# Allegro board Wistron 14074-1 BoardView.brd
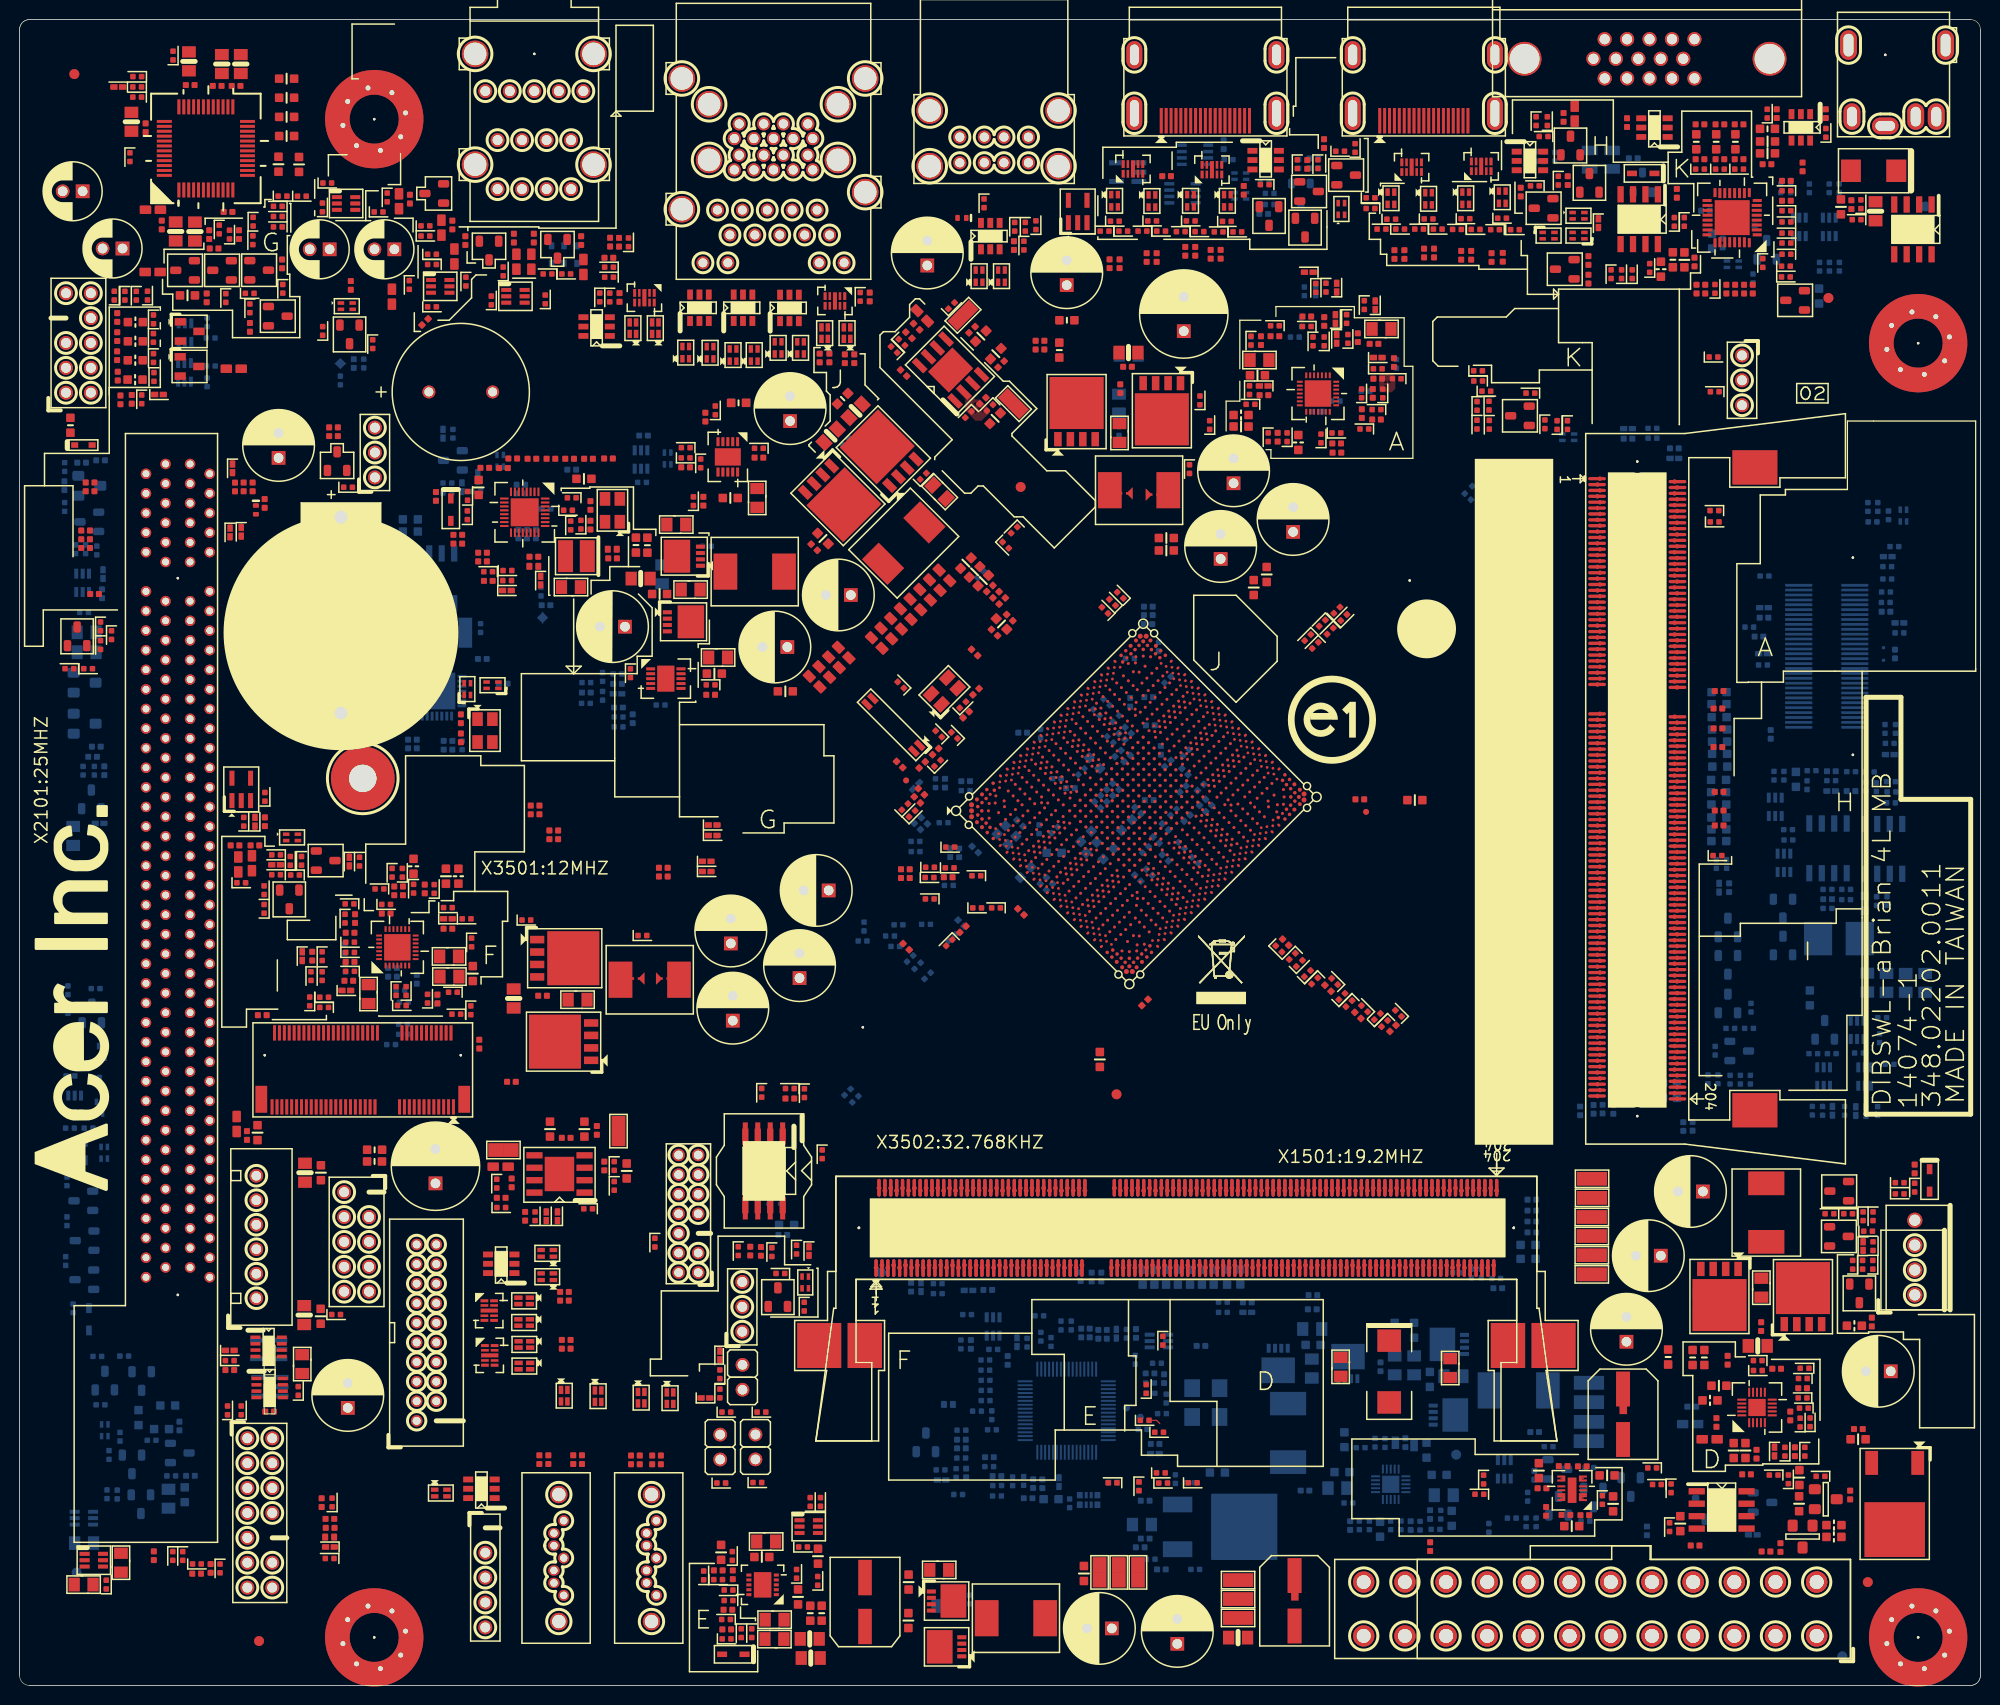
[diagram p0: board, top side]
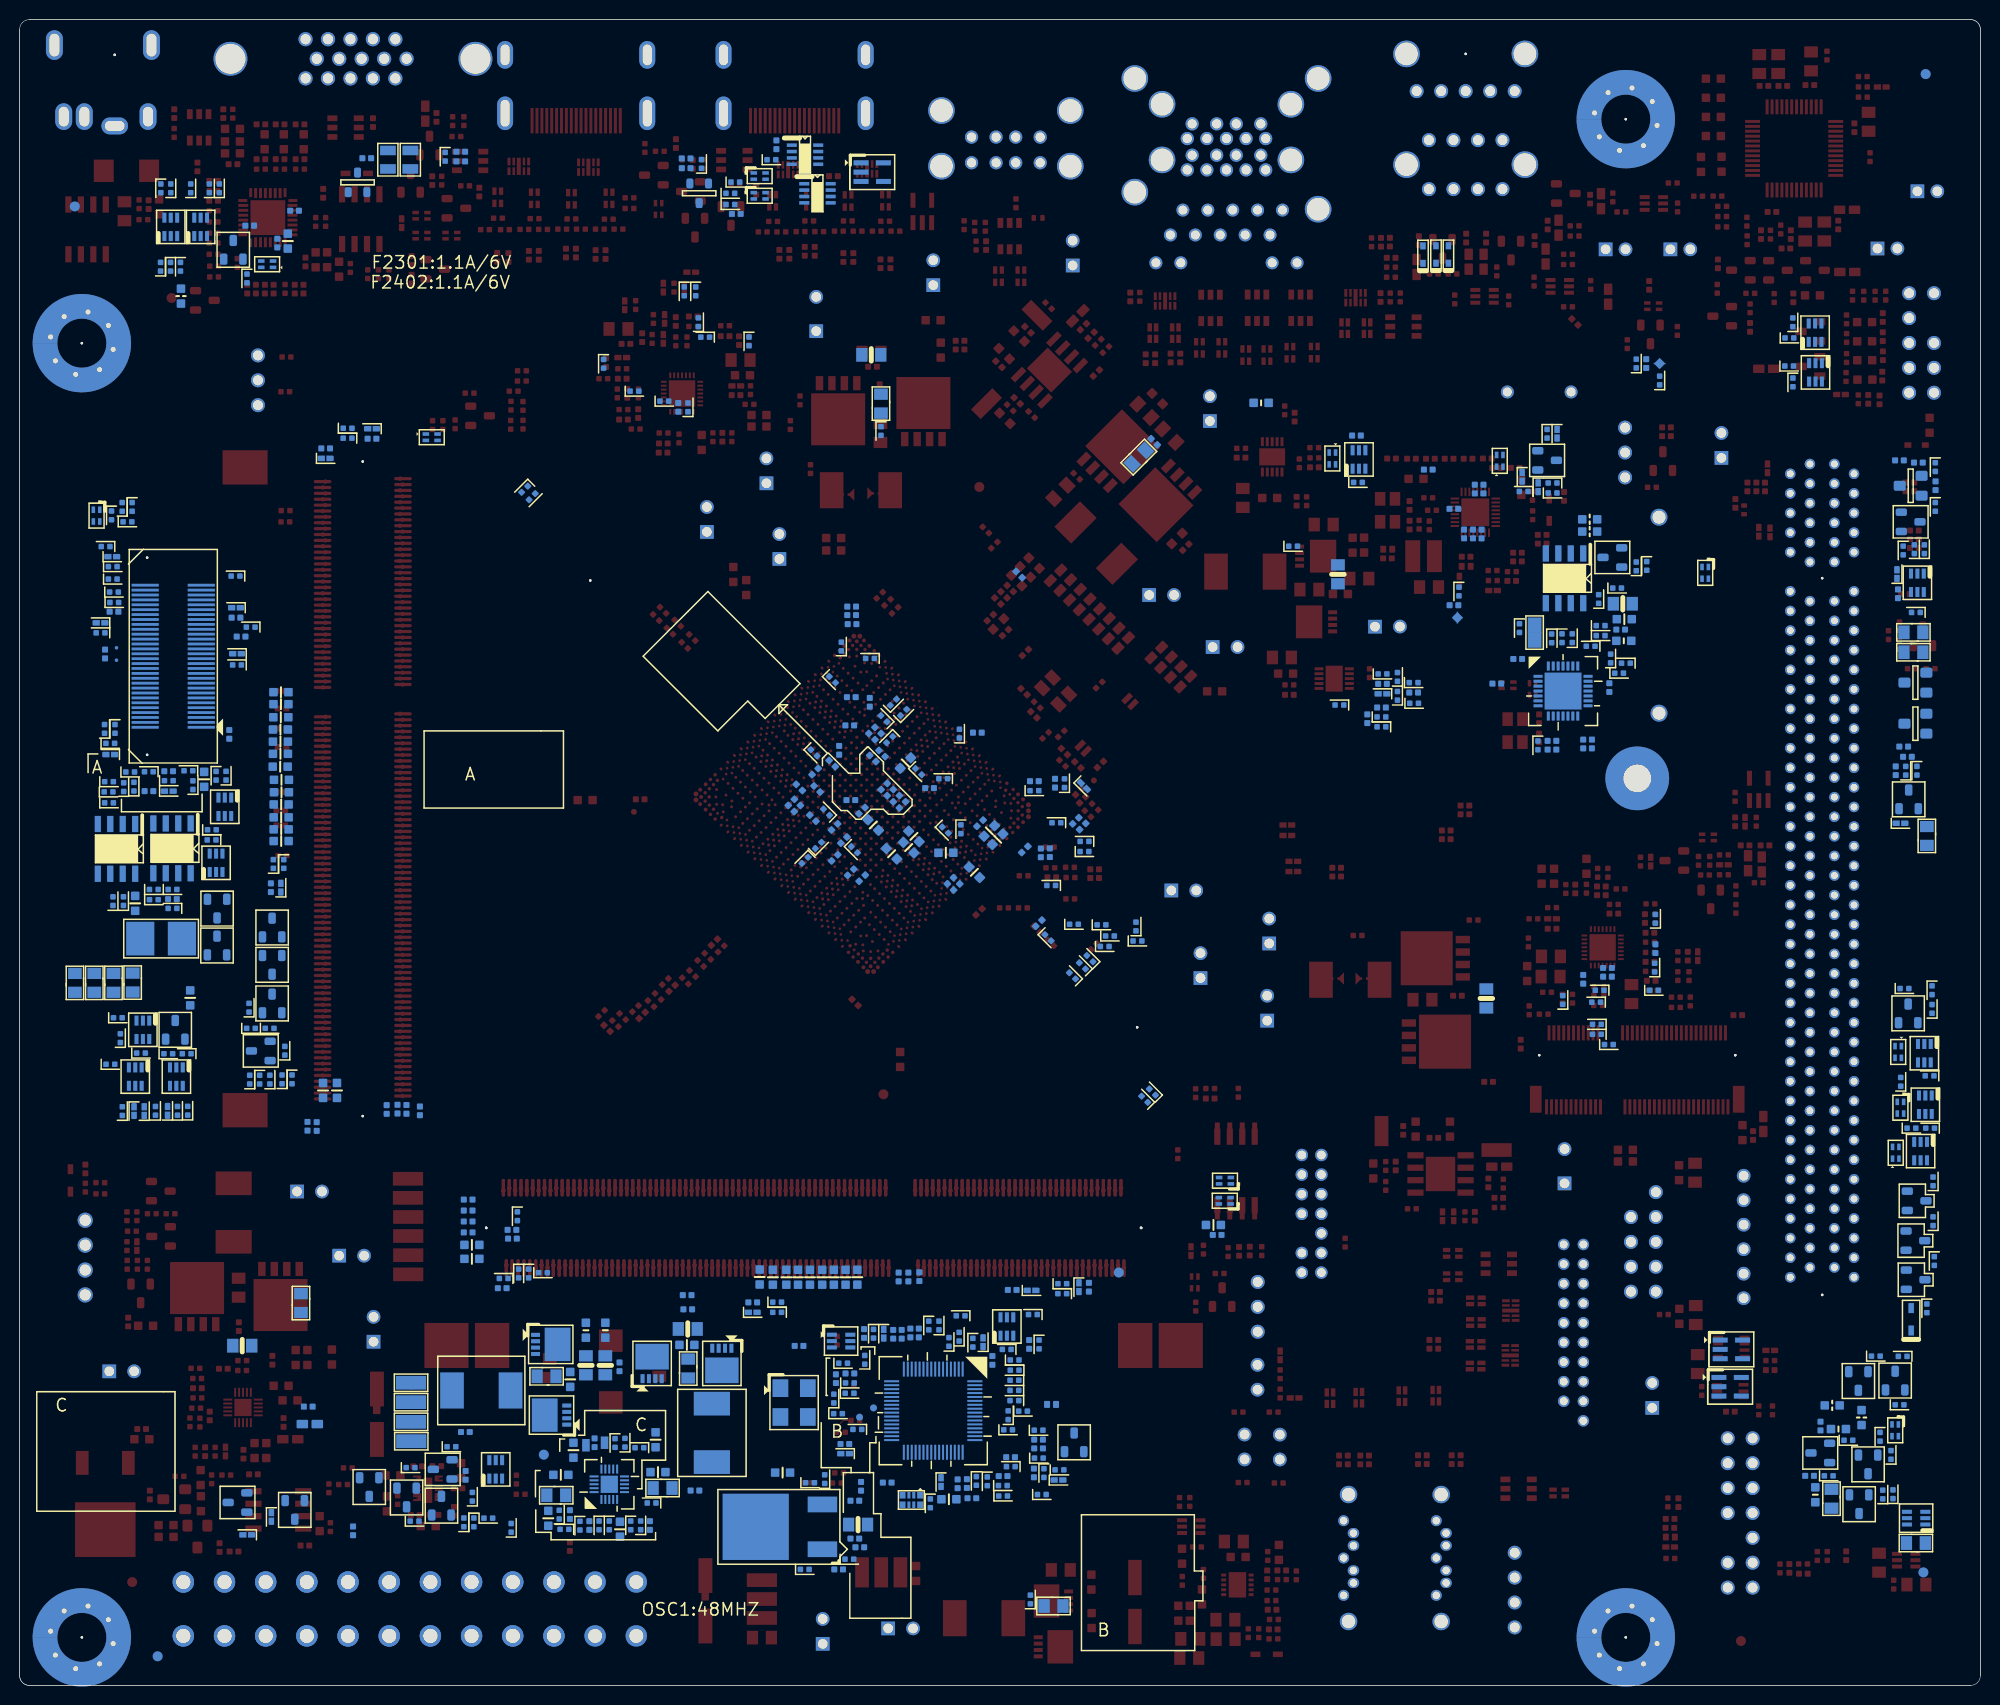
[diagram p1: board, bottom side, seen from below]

Outline 200 x 170 mm; copper layers: TOP, L2VCC, L3, BOTTOM. Coordinates in mm from the lower left corner of the outline.
Outline path: 0,169 0,1 ; 0,169 arc(0.29,169.71) 1,170 ; 0,169 arc(0.29,169.71) 1,170 ; 0,169 0,1 ; 0,1 arc(0.29,0.29) 1,0 ; 1,170 199,170 ; 1,170 199,170 ; 199,170 arc(199.71,169.71) 200,169 ; 1,0 199,0 ; 1,0 199,0 ; 199,0 arc(199.71,0.29) 200,1 ; 199,0 arc(199.71,0.29) 200,1 ; 200,169 200,1 ; 200,169 200,1 ; 33.62,92.57 arc(35,93.95) 36.38,92.57 arc(35,91.19) 33.62,92.57

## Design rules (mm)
constraint set DEFAULT: min track width 0.127, pair gap 0.102
net group POWER_50_8: nets -12V SIO_GND
net group PWR_300_10: nets +3D3V_PWR +5V_PWR
net group PWR_500_10: nets 1D35V_DDR 1P05V_A
net group 50_VGA: nets CRT_B CRT_G CRT_HSYNC_CON CRT_R CRT_VSYNC_CON VGA_BLUE_P VGA_GREEN_P VGA_HSYNC VGA_RED_P VGA_VSYNC
net group AUDIO_4_6: nets 3.3_POP ANTI-POP_GPIO1 ANTI-POP_GPIO1_L ANTI-POP_GPIO1_R AZRST EAPD_DEPOP FP_AUDIO_PRESENCE*_C FP_AUDIO_PRESENCE_N_1 FP_OUTR_SENSE FRONT_JD HDA_SPKR JDREF LINE2_JD LINEIN_JD MIC1_JD MIC2_JD MUTE_R MUTE_RR PCH_SPKR1 SENSE_A SENSE_B
net group AUDIO_8_10: nets AUD_IN_L AUD_IN_LL AUD_IN_LL* AUD_IN_LL_1 AUD_IN_R AUD_IN_RR AUD_IN_RR* AUD_IN_RR_1 AUD_MIC1_L AUD_MIC1_LL AUD_MIC1_LL* AUD_MIC1_LL_1 AUD_MIC1_R AUD_MIC1_RR AUD_MIC1_RR* AUD_MIC1_RR_1 AUD_MIC_1L AUD_MIC_1R AUDAMPIN_L AUDAMPIN_L_C AUDAMPIN_R AUDAMPIN_R_C AUDIN_L AUDIN_R FB_AUDOUT_L FB_AUDOUT_R FB_AUDOUTR_L FB_AUDOUTR_L* FB_AUDOUTR_R FB_AUDOUTR_R* FP_MIC2_L FP_MIC2_L_C FP_MIC2_R FP_MIC2_R_C FP_MICVREF_D1 FP_MICVREF_D2 FP_OUT_L FP_OUT_L_C FP_OUT_LL* FP_OUT_R FP_OUT_R_C FP_OUT_RR* FP_OUTR_L FP_OUTR_LL FP_OUTR_R FP_OUTR_RR LINE2_VREFO LINE2_VREFO_D1 LINE2_VREFO_D2 MIC1_VREFO_L MIC1_VREFO_R MIC2-VREFO MIC2_L MIC2_LL MIC2_LL* MIC2_R MIC2_RR MIC2_RR* MUTE
net group CLK_4_12: nets CLK_PCI_DEBUG CLKIN HDA_BITCLK_CODEC HDA_BITCLK_CPU INT_SERIRQ_CPU INT_SERIRQ_OE LPC_CLKOUT0 LPC_CLKOUT1 OSC_TRI PCH_CLK48 PCH_SPI_CLK PCH_SPI_CLK_FLASH PM_CLKRUN# PMU_SUSCLK_CPU SERIRQ_N SIO_CLKIN SIO_PCICLK
net group FAN_4_12: nets CPU_FAN_PWM1 CPU_FAN_TACH1 SYS_FAN_3P_G SYS_FAN_M SYS_FAN_M1 SYS_FAN_TACH1_1 SYS_FAN_TACH1_2 SYSTEM_FAN_PWM1_1 SYSTEM_FAN_PWM1_2 SYSTEM_FAN_PWM1_3
net group HDA_4_6: nets HDA_RST#_CODEC HDA_RST#_CPU HDA_SDIN0_CODEC HDA_SDIN0_CPU HDA_SDOUT_CODEC HDA_SDOUT_CPU HDA_SYNC_CODEC HDA_SYNC_CPU
net group LED_8_8: nets HD_LED_PWR LAN_LED* LAN_LED*_EMI LAN_LED_ACT LAN_LED_ACT_C LAN_LED_ACTIVE LAN_LEDC0 LAN_LEDC1 LAN_LEDC1_E LAN_LEDC1_E1 LAN_LINK_100 LAN_LINK_100_R LAN_LINK_1000 LAN_LINK_1000_R NGFF_LED_BT NGFF_LED_WLAN PWR_LEDC1 PWR_LEDC1_D PWR_LEDJ_C PWR_LEDJ_L PWR_LEDJ_P SATA_LED# SATA_LED_OUT SATA_LED_OUT1
net group LPC_PORT_4_8: nets LAD0_FWH0 LAD1_FWH1 LAD2_FWH2 LAD3_FWH3 LFRAMEJ_FW4 PORT80_SW
net group M_A_CLK_1: nets M_A_DIM1_CLK_DDR1
net group M_A_CMD-CLK: nets M_A_A0 M_A_A1 M_A_A2 M_A_A3 M_A_A4 M_A_A5 M_A_A6 M_A_A7 M_A_A8 M_A_A9 M_A_A10 M_A_A11 M_A_A12 M_A_A13 M_A_A14 M_A_A15 M_A_BS0 M_A_BS1 M_A_BS2 M_A_CAS# M_A_RAS# M_A_WE#
net group M_A_CTRL-CLK: nets M_A_DIM1_CKE0 M_A_DIM1_CKE1 M_A_DIM1_CS#0 M_A_DIM1_CS#1 M_A_DIM1_ODT0 M_A_DIM1_ODT1
net group M_A_DATA_0: nets M_A_DIM1_DM0 M_A_DQ0 M_A_DQ1 M_A_DQ2 M_A_DQ3 M_A_DQ4 M_A_DQ5 M_A_DQ6 M_A_DQ7 M_A_DQS_DN0 M_A_DQS_DP0
net group M_A_DATA_1: nets M_A_DIM1_DM1 M_A_DQ8 M_A_DQ9 M_A_DQ10 M_A_DQ11 M_A_DQ12 M_A_DQ13 M_A_DQ14 M_A_DQ15
net group M_A_DATA_2: nets M_A_DIM1_DM2 M_A_DQ16 M_A_DQ17 M_A_DQ18 M_A_DQ19 M_A_DQ20 M_A_DQ21 M_A_DQ22 M_A_DQ23
net group M_A_DATA_3: nets M_A_DIM1_DM3 M_A_DQ24 M_A_DQ25 M_A_DQ26 M_A_DQ27 M_A_DQ28 M_A_DQ29 M_A_DQ30 M_A_DQ31 M_A_DQS_DN3
net group M_A_DATA_4: nets M_A_DIM1_DM4 M_A_DQ32 M_A_DQ33 M_A_DQ34 M_A_DQ35 M_A_DQ36 M_A_DQ37 M_A_DQ38 M_A_DQ39
net group M_A_DATA_5: nets M_A_DIM1_DM5 M_A_DQ40 M_A_DQ41 M_A_DQ42 M_A_DQ43 M_A_DQ44 M_A_DQ45 M_A_DQ46 M_A_DQ47 M_A_DQS_DP5
net group M_A_DATA_6: nets M_A_DIM1_DM6 M_A_DQ48 M_A_DQ49 M_A_DQ50 M_A_DQ51 M_A_DQ52 M_A_DQ53 M_A_DQ54 M_A_DQ55
net group M_A_DATA_7: nets M_A_DIM1_DM7 M_A_DQ56 M_A_DQ57 M_A_DQ58 M_A_DQ59 M_A_DQ60 M_A_DQ61 M_A_DQ62 M_A_DQ63
net group M_B_CMD-CLK: nets M_B_A0 M_B_A1 M_B_A2 M_B_A3 M_B_A4 M_B_A5 M_B_A6 M_B_A7 M_B_A8 M_B_A9 M_B_A10 M_B_A11 M_B_A12 M_B_A13 M_B_A14 M_B_A15 M_B_BS0 M_B_BS1 M_B_BS2 M_B_CAS# M_B_RAS# M_B_WE#
net group M_B_CTRL_CLK: nets M_B_DIM2_CKE0 M_B_DIM2_CKE1 M_B_DIM2_CS#0 M_B_DIM2_CS#1 M_B_DIM2_ODT0 M_B_DIM2_ODT1
net group M_B_DATA_0: nets M_B_DIM2_DM0 M_B_DQ0 M_B_DQ1 M_B_DQ2 M_B_DQ3 M_B_DQ4 M_B_DQ5 M_B_DQ6 M_B_DQ7
net group M_B_DATA_1: nets M_B_DIM2_DM1 M_B_DQ8 M_B_DQ9 M_B_DQ10 M_B_DQ11 M_B_DQ12 M_B_DQ13 M_B_DQ14 M_B_DQ15
net group M_B_DATA_2: nets M_B_DIM2_DM2 M_B_DQ16 M_B_DQ17 M_B_DQ18 M_B_DQ19 M_B_DQ20 M_B_DQ21 M_B_DQ22 M_B_DQ23
net group M_B_DATA_3: nets M_B_DIM2_DM3 M_B_DQ24 M_B_DQ25 M_B_DQ26 M_B_DQ27 M_B_DQ28 M_B_DQ29 M_B_DQ30 M_B_DQ31
net group M_B_DATA_4: nets M_B_DIM2_DM4 M_B_DQ32 M_B_DQ33 M_B_DQ34 M_B_DQ35 M_B_DQ36 M_B_DQ37 M_B_DQ38 M_B_DQ39
net group M_B_DATA_5: nets M_B_DIM2_DM5 M_B_DQ40 M_B_DQ41 M_B_DQ42 M_B_DQ43 M_B_DQ44 M_B_DQ45 M_B_DQ46 M_B_DQ47
net group M_B_DATA_6: nets M_B_DIM2_DM6 M_B_DQ48 M_B_DQ49 M_B_DQ50 M_B_DQ51 M_B_DQ52 M_B_DQ53 M_B_DQ54 M_B_DQ55
net group M_B_DATA_7: nets M_B_DIM2_DM7 M_B_DQ56 M_B_DQ57 M_B_DQ58 M_B_DQ59 M_B_DQ60 M_B_DQ61 M_B_DQ62 M_B_DQ63
net group OCP_4_8: nets ADP_OCP OCP_0 OCP_1 OCP_2 OCP_3 OCP_4 OCP_5 OCP_6 OCP_7 OCP_8
net group OTHER_4_5: nets AC_PRESENT_CPU BOARD1 BVCCRTC_EXTPAD CFG0 CFG1 CFG2 CFG3 CFG4 CFG5 CFG6 CFG7 CFG8 COPEN_N CPU_VSS2 CPU_VSS16 DP_HPD_CPU# DP_HPD_RTD2168 DSW_EUP_SEL EDM_SOC EEPROM_WP FP_AUDIO_PRESENCE_N FP_RESET*_R GFX_CLKREQ_CPU# GFX_CLKREQ_CPU#_1D8 GFX_REQ#_Q_B GP_CAMERASB00 GP_CAMERASB01 GP_CAMERASB02 GP_CAMERASB03 GP_CAMERASB04 GP_CAMERASB05 GP_CAMERASB06 GP_CAMERASB07 GP_CAMERASB08 GP_CAMERASB09 GP_CAMERASB11 GPIO_SUS1 GPIO_SUS2 GPIO_SUS3 GPIO_SUS4 GPIO_SUS5 H_PROCHOT# H_PROCHOT#_R HDMI1_DDCCLK_G HDMI1_DDCDATA_G HDMI1_HPD_CON HDMI1_HPD_CPU# HDMI2_DDCCLK_G HDMI2_DDCDATA_G HDMI2_HPD_CON HDMI2_HPD_CPU# HUB_OC14_L HUB_OC23_L HUB_PGANG HUB_PSELF KA20GATE KBCLK KBDATA KBRST_N LAN_CLKREQ_CPU# LAN_CLKREQB LAN_WAKEB LOM_WAKE_N_CPU LOM_WAKE_N_CPU1 LOM_WAKE_N_CPU2 MSCLK MSDATA PCH_SPI_WP# PCH_SPI_WP#_FLASH PCIE_CLKREQ2_CPU#_1D8 PCIE_PRSNT1# PCIE_WAKE_LOM PCIE_WAKE_LOM1 PCIE_WAKE_N_CPU PCIE_WAKE_N_CPU1 PCIE_WAKE_N_CPU2 PCIE_WAKE_N_CPU3 PCIE_WAKE_N_MINI PCIE_WAKE_N_X16 PCU_SMB_ALERT# RSVD# RTD2168_RRX RTD2168_SMBUS_ON RTD2168_SMBUS_ON_1 SDMMC1_RCOMP SDMMC3_RCOMP SEC_GPIO_SUS8 SEC_GPIO_SUS9 SEC_GPIO_SUS10 SIO_GP31 SIO_GP31_R SIO_GP32 SIO_GP32_R SOC_EXTSMI_N SOC_RUNTIME_SCI# SOC_WAKE_SCI_N SP1_DCD_N SP1_DTR_N SP1_RTS_N SP1_RXD SP1_TXD SPI_WP_N_PU SUS_PWRDN_ACK_CPU THERMAL_SHUT# THERMAL_SHUT#_1 TXE_1 TXE_2 USB_OC#_0 USB_OC#_1 USB_OTG_ID USB_VBUSSNS VSS5 W1_DISABLE_N W3_DISABLE W3_DISABLE_N WLAN_CLKREQ_CPU# WLAN_CLKREQ_CPU#_1D8 WLAN_REQ#_Q_B
net group OTHER_4_8: nets GPIO_RCOMP18 HDMI1_LS_R HDMI2_LS_R HUB_RESET# HUB_RREF HUB_SDA HUB_TEST/SCL ICLKICOMP ICLKRCOMP LAN_ISOLATEB LAN_RSET LPC_PME_N M_A_RCOMP_0 M_B_RCOMP_0 MCSI_COMP NGFF_SUSCLK PCH_SPI_CS0# PCH_SPI_CS0#_FLASH PCH_SPI_HOLD# PCH_SPI_HOLD#_FLASH PCH_SPI_SI PCH_SPI_SI_FLASH PCH_SPI_SO PCH_SPI_SO_FLASH PM_EXTTS#0 PM_EXTTS#1 PMC_BATLOW# RCOMP_LPC_HVT RTC_INTRUDER RTD2168_LDO_EN SA0_A_0 SA0_B_0 SA1_A_0 SA1_B_0 SIO_PWRLED_N USB30_VCCA_0_EN USB30_VCCA_1_EN USB_HSIC_RCOMP USB_RCOMP USBVCC4_EN USBVCC23_EN VGG_VR_HOT# VNN_VCC_SEN
net group OTHER_10_8: nets DIMM1_VREF_CA DIMM1_VREF_CA_R DIMM1_VREF_DQ DIMM1_VREF_DQ_R DIMM2_VREF_CA DIMM2_VREF_CA_R DIMM2_VREF_DQ DIMM2_VREF_DQ_R DISCHARGE_A DISCHARGE_B DISCHARGE_C DISCHARGE_M M_A_OCAVREF M_A_OCAVREF_R M_A_ODQVREF M_A_ODQVREF_R M_B_OCAVREF M_B_OCAVREF_R M_B_ODQVREF M_B_ODQVREF_R SIO_VCORE SIO_VIN0 SIO_VIN1 SIO_VIN2 SIO_VIN3 SIO_VIN4
net group POWER20: nets SYS_FAN_3P_POWER
net group POWER25_8: nets AUDIO_VREF
net group POWER25_40: nets PWR_1D8V_BOOT PWR_1D8V_BOOT_1 PWR_1D8V_HG PWR_1D8V_HG_1 PWR_1D8V_LG PWR_1D8V_LX PWR_1P05V_BOOT PWR_1P05V_BOOT_1 PWR_1P05V_HG PWR_1P05V_HG_1 PWR_1P05V_LG PWR_1P05V_LX PWR_12V_BOOT PWR_12V_BOOT1 PWR_12V_BT1 PWR_12V_LG PWR_12V_LX PWR_12V_UG PWR_12V_UG1 PWR_DDR_BT PWR_DDR_BT1 PWR_DDR_LG PWR_DDR_LX PWR_DDR_UG PWR_DDR_UG1 PWR_RT8243_BT1 PWR_RT8243_BT1R PWR_RT8243_BT2 PWR_RT8243_BT2R PWR_RT8243_LG1 PWR_RT8243_LG2 PWR_RT8243_LX1 PWR_RT8243_LX2 PWR_RT8243_UG1 PWR_RT8243_UG1R PWR_RT8243_UG2 PWR_RT8243_UG2R PWR_VCC0_BT PWR_VCC0_BTR PWR_VCC0_HG PWR_VCC0_HGR PWR_VCC0_LG PWR_VGG_BT PWR_VGG_BTR PWR_VGG_HG PWR_VGG_HGR PWR_VGG_LG PWR_VGG_SW
net group POWER_7_10: nets VCC0_VCC_SEN VCC0_VSS_SEN VGG_VCC_SEN VGG_VSS_SEN
net group POWER_10_10: nets +VCCCLKDDR_1P24_1P35 +VCCPADCF3SI0_1P8_3P3 +VCCSFRPLLDDR_1P24_1P35 LEDH1_5V PWR_0D675V_EN_S3 PWR_1D5V_EN PWR_1D8V_CS PWR_1D8V_EN PWR_1D8V_RF PWR_1D24V_CNTL PWR_1D24V_EN PWR_1D35V_EN_S5 PWR_1P05V_CS PWR_1P05V_EN PWR_1P05V_EN1 PWR_1P05V_EN2 PWR_1P05V_RF PWR_1P15V_CNTL PWR_1P15V_EN PWR_12V_COMP PWR_12V_CP1 PWR_12V_VOS PWR_AD+_2 PWR_DDR_CS PWR_DDR_TON PWR_DDR_VTTREF PWR_RT8243_EMN PWR_RT8243_ENLDO PWR_RT8243_ENTRIP1 PWR_RT8243_ENTRIP2 PWR_RT8243_PG PWR_VCC0_COMP PWR_VCC0_COMP1 PWR_VCC0_COMP2 PWR_VCC0_CSCOMP PWR_VCC0_CSMP1 PWR_VCC0_CSREF PWR_VCC0_CSSUM PWR_VCC0_DIFFOUT PWR_VCC0_ILIM PWR_VCC0_IMAX PWR_VCC0_IOUT PWR_VCC0_ROSC PWR_VCC0_TSEN PWR_VCC0_TSEN1 PWR_VCC0_VBOOT/ADDR PWR_VCC0_VRMP PWR_VCORE_ENABLE PWR_VGG_COMP PWR_VGG_COMP1 PWR_VGG_COMP2 PWR_VGG_CSCOMP PWR_VGG_CSMP1 PWR_VGG_CSREF PWR_VGG_CSSUM PWR_VGG_DIFFOUT PWR_VGG_ENABLE PWR_VGG_ILIM PWR_VGG_IMAX PWR_VGG_IOUT PWR_VGG_ROSC PWR_VGG_TSEN PWR_VGG_TSEN1 PWR_VGG_VBOOT/ADDR PWR_VGG_VRMP SYS_FAN_FB USB_VDDQ_G31_H44 VCORE_VR_HOT
net group POWER_10_10_20: nets PWR_VCC0_CSN PWR_VCC0_CSP PWR_VCC0_VSN PWR_VCC0_VSP PWR_VGG_CSN PWR_VGG_CSP PWR_VGG_VSN PWR_VGG_VSP
net group POWER_15_20: nets 1D5V_S0 PWR_1D8V_FB PWR_1P05V_FB PWR_1P15V_FB PWR_12V_FB PWR_12V_FB1 PWR_DDR_FB PWR_RT8243_3VFB PWR_RT8243_FB1 PWR_RT8243_FB2 PWR_RT8243_TON PWR_VCC0_FB PWR_VGG_FB
net group POWER_20_10: nets 1D8V_DDI 1D8V_S0 5V_DDC_HDMI11 5V_DDC_HDMI12 5V_DDC_HDMI21 5V_DDC_HDMI22 +3VL +5VL +VCCCFIOAZA_1P80 AD_JK_S AVDD2 BZ_ON BZ_ON1 LDOVDD_IN P_LAN_VDDREG_IN PWR_1D5V_VIN PWR_1D8V_SN PWR_1D8V_VCC PWR_1P05V_SN PWR_1P05V_VCC PWR_12V_SNB PWR_12V_VCC PWR_DDR_SNB PWR_DDR_VDD PWR_DDR_VDDQ PWR_RT8243_BYP1 PWR_RT8243_LDO3 PWR_RT8243_LDO5 PWR_RT8243_SNB1 PWR_RT8243_SNB2 PWR_VCC0_PVCC PWR_VCC0_SN PWR_VCC0_VCC PWR_VGG_PVCC PWR_VGG_SN PWR_VGG_VCC RTD2168_AVCC12 RTD2168_AVCC33 RTD2168_DAC33 V1P5_PWR VGA_DDC_PU
net group POWER_30_10: nets 1D05V_LAN 3D3V_LAN 3D3V_NGFF 3VSB_DET 5V_HUB HUB_AVDD HUB_DVDD LAN_CONN_CVT P_1.05VLAN_OUT VCC3_3SBREF
net group PWR_12_10: nets 1D8V_SPI
net group PWR_40_10: nets 1D15V_S5 1D24V_S5 1P15V_A 3D3V_RTD2168 3D3V_S5_PRIME 5V_HDMI 5V_S0_VGA PWR_1D24V_A PWR_1D24V_VIN PWR_1P15V_VIN USB30_VCCA_0 USB30_VCCA_1 USBVCC4 USBVCC23
net group PWR_80_10: nets 0D675V_S0 12V_VIN +DCBATOUT_RT8243_1 PWR_1D8V_VIN PWR_DDR_LDOIN PWR_DDR_VTT PWR_VGG_VIN
net group PWR_200_10: nets +12V DDR_1D35VIN PWR_1D8V_A PWR_1P05V_VIN
net group RTC_6_10: nets RTC_AUX_S5 VBAT VBAT1 VBAT_SIO
net group SEQUENCE_4_8: nets 1D05V_S5_PG 1D8V_S0_EN1 1D8V_S0_EN2 1D8V_S5_PG 1D15V_S5_PG 1D24V_S5_PG 1D35V_S3_PG 3D3V_S5_PRIME_EN1 3D3V_S5_PRIME_EN2 3D3V_S5_PRIME_EN3 5V_DUAL_EN1 5V_DUAL_EN2 5V_DUAL_EN3 5V_DUAL_EN4 5V_DUAL_EN5 5V_DUAL_EN6 5V_DUAL_EN_5VSB 5V_DUAL_EN_12V 5VSB_CTRL# ADP_12V_S0_PG ADP_EUPPWR_EN1 ADP_EUPPWR_EN2 ADP_EUPPWR_EN3 ADP_EUPPWR_EN4 ADP_EUPPWR_EN5 ADP_EUPPWR_EN6 ADP_EUPPWR_EN7 ADP_NORMPWR_EN ATX_ON1* ATX_ON* ATX_PWRGD ATX_PWRGD_SIO COREPWROK DDR3_DRAM_PWROK DDR3_DRAM_PWROK1 DDR3_DRAM_PWROK2 DDR3_VCCA_PWRGD_3D3V DDR3_VCCA_PWROK DDR3_VCCA_PWROK1 DIMM1_DRAMRST# DIMM2_DRAMRST# M_A_DRAMRST# M_B_DRAMRST# PCIE_RST_X1 PCIRST_LAN# PLT_RST# PLT_RST#_CPU PLT_RST#_CPU1 PLT_RST#_CPU2 PLT_WLAN_RST# PLTRST_SIO_N PM_PWRBTN#_CPU PM_PWRBTN#_CPU1 PM_SLP_S0IX PM_SLP_S0IX_CPU PM_SLP_S0IX_CPU1 PM_SLP_S0IX_CPU2 PM_SLP_S3#_CPU PM_SLP_S4#_CPU PMC_RSTBTN# PWR_12V_ENABLE1 PWR_12V_ENABLE2 PWR_BTN_N PWR_BTNJ_C PWRGD3V_150MS PWRGD_PS_L PWRGD_PS_L1 RSMRST#_CPU RSMRST#_R RSMRST_N RTC_RST#_DOWN SIO_EUP_EN SIO_LAN_RST SIO_PB_IN SIO_PSON_N SIO_PSON_N_1 SIO_PWNBTN_N SIO_PWRGD SLP_S3#_LS1 SLP_S3#_LS2 SLP_S3_N SLP_S3_N_B SLP_S4#_LS1 SLP_S4#_LS2 SLP_S4_N SYS_PWRGD SYS_PWRGD1 SYS_PWRGD2 SYS_PWRGD3 SYS_PWRGD4 VCORE_PG VGG_PG VTT_CT_3.3V_NORM VTT_CT_5VC_NORM
net group SIO_SYS_THERMDA: nets HWM_REF SYS_THERMDA VRD_THERMDA
net group SMB_4_10: nets APU_SIC APU_SID CIIC_SCL CIIC_SDA CRT_DDCCLK_CON CRT_DDCDATA_CON HDMI1_DDCCLK_CON HDMI1_DDCCLK_CPU HDMI1_DDCDATA_CON HDMI1_DDCDATA_CPU HDMI2_DDCCLK_CON HDMI2_DDCCLK_CPU HDMI2_DDCDATA_CON HDMI2_DDCDATA_CPU POL1_SDA POL2_SCL SMB_CLK SMB_CLK_2168 SMB_CLK_CPU SMB_CLK_M SMB_CLK_MINI SMB_CLK_XDP SMB_DATA SMB_DATA_2168 SMB_DATA_CPU SMB_DATA_M SMB_DATA_MINI SMB_DATA_XDP UART0_RXD UART0_TXD UART_RXD UART_TXD VGA_DDC_CLK VGA_DDC_DATA
net group SVID_4_15: nets SVID_ALERT#_CPU SVID_ALERT#_VCORE SVID_ALERT#_VGG SVID_CLK_CPU SVID_CLK_VCORE SVID_CLK_VGG SVID_DATA_CPU SVID_DATA_VCORE SVID_DATA_VCORE_R SVID_DATA_VGG SVID_DATA_VGG_R
net group XDP_4_5: nets PM_PWRBTN#_XDP TP_CLK_ITP_100M_CK505_DN TP_CLK_ITP_100M_CK505_DP XDP_COREPWROK XDP_HLT_BOOT XDP_PMU_RSTBTN_N XDP_PRDY# XDP_PREQ# XDP_PREQ#_C XDP_PRESENT_N XDP_RSMRST_N XDP_RST#_R XDP_TCK XDP_TDI XDP_TDO XDP_TMS XDP_TRST#
net group XTAL_4_12: nets BLAN_XTALI BLAN_XTALI_1 BLAN_XTALO HUB_X1 HUB_X2 RTC_RST# RTC_X1 RTC_X2 SRTC_RST# XTAL19D2M_IN XTAL19D2M_OUT

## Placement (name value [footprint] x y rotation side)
ATX1  JWT-CONN24B-S1-GP  [C4201WV0-B2X12P]  160.2 7.8 180 top
ATX2  TCN-CONN20B-1GP  [PPA12635GD210F]  164.4 7.8 180 top
AUDH1  JWT-CONN10D-SFP7-GP  [1E450400]  6 137 270 top
AUDIO1  ALC662-GR-GP  [PFPCC48-1H63]  19 156.85 180 top
AUDR1  AUDIO-JK187-GP  [ABA-JAK-028-K03]  52.5 166.5 0 top
BT1  BAT-AAA-BAT-029-K01-GP-U  [AAA-BAT-029-K01]  32.78 107.42 90 top
BUZ1  BUZZER-17-GP-U  [AC-1205G-N1LF-U]  45 132 90 top
C20  SCD1U16V2KX-3GP  [C402H22]  181.86 154.97 0 top
C501  SCD1U16V2KX-3GP  [C402H22]  136.5 68.38 225 top
C502  SCD1U16V2KX-3GP  [C402H22]  133.45 71.15 225 top
C503  SCD1U16V2KX-3GP  [C402H22]  129.13 75.84 225 top
C504  SCD1U16V2KX-3GP  [C402H22]  140.08 67.06 315 top
C1001  SC1U10V2KX-1GP  [C402H22]  111.2 91.11 45 bottom
C1002  SC1U10V2KX-1GP  [C402H22]  98.96 111.94 135 top
C1003  SC1U10V2KX-1GP  [C402H22]  98.05 113.36 315 bottom
C1004  SC1U10V2KX-1GP  [C402H22]  116.86 84.46 225 bottom
C1005  SC1U10V2KX-1GP  [C402H22]  112.44 97.46 315 bottom
C1006  SC1U10V2KX-1GP  [C402H22]  113.07 96.83 315 bottom
C1007  SC1U10V2KX-1GP  [C402H22]  100.99 108.97 45 top
C1008  SC1U10V2KX-1GP  [C402H22]  99.59 111.3 135 top
C1009  SC22U6D3V3MX-1-GP  [C603H40]  98.3 112.75 135 top
C1010  SC22U6D3V3MX-1-GP  [C603H40]  97.41 113.64 135 top
C1011  SC22U6D3V3MX-1-GP  [C603H40]  96.52 114.53 135 top
C1012  SC22U6D3V3MX-1-GP  [C603H40]  100.15 108.32 45 top
C1013  SC1U10V2KX-1GP  [C402H22]  110.58 90.49 45 bottom
C1017  SC1U10V2KX-1GP  [C402H22]  119.09 88.51 315 bottom
C1018  SC1U10V2KX-1GP  [C402H22]  97.41 105.41 45 top
C1020  SC1U10V2KX-1GP  [C402H22]  111.82 91.74 45 bottom
C1022  SC1U10V2KX-1GP  [C402H22]  109.95 89.86 45 bottom
C1024  SC1U10V2KX-1GP  [C402H22]  99.44 107.44 45 top
C1025  SC1U10V2KX-1GP  [C402H22]  100.23 110.67 135 top
C1026  SC1U10V2KX-1GP  [C402H22]  90.42 75.39 225 top
C1027  SC1U10V2KX-1GP  [C402H22]  118.86 93.26 45 bottom
C1030  SC1U10V2KX-1GP  [C402H22]  114.08 89.28 45 bottom
C1031  SC10U6D3V3MX-GP  [C603H38]  105.52 84.97 90 bottom
C1032  SC1U10V2KX-1GP  [C402H22]  117.12 94.08 315 bottom
C1033  SC1U10V2KX-1GP  [C402H22]  116.41 95.43 0 bottom
C1034  SC1U10V2KX-1GP  [C402H22]  104.42 81.48 225 bottom
C1035  SC1U10V2KX-1GP  [C402H22]  96.04 77.79 45 bottom
C1037  SC1U10V2KX-1GP  [C402H22]  120.47 91.64 315 bottom
C1040  SC22U6D3V3MX-1-GP  [C603H40]  125.88 112.04 0 top
C1041  SC22U6D3V3MX-1-GP  [C603H40]  116.97 115.82 270 top
C1042  SC22U6D3V3MX-1-GP  [C603H40]  127.2 113.37 0 top
C1043  SC10U6D3V3MX-GP  [C603H38]  102.61 82.98 135 bottom
C1044  SC10U6D3V3MX-GP  [C603H38]  111.06 84.87 135 bottom
C1045  SC10U6D3V3MX-GP  [C603H38]  109.32 85.5 135 bottom
C1046  SC10U6D3V3MX-GP  [C603H38]  112.93 87.81 315 bottom
C1047  SC1U10V2KX-1GP  [C402H22]  105.05 82.12 225 bottom
C1048  SC22U6D3V3MX-1-GP  [C603H40]  116.97 117.09 270 top
C1049  SC10U6D3V3MX-GP  [C603H38]  108.78 86.64 135 bottom
C1056  SC1U10V2KX-1GP  [C402H22]  112.03 95.1 135 bottom
C1057  SC1U10V2KX-1GP  [C402H22]  112.97 94.59 135 bottom
C1102  SC1U10V2KX-1GP  [C402H22]  102.13 78.94 225 top
C1103  SC1U10V2KX-1GP  [C402H22]  102.31 97.23 270 bottom
C1104  SC22U6D3V3MX-1-GP  [C603H40]  100.24 86.36 225 bottom
C1105  SC1U10V2KX-1GP  [C402H22]  95.83 84.96 180 bottom
C1108  SC1U10V2KX-1GP  [C402H22]  113.28 100.33 180 bottom
C1110  SC1U10V2KX-1GP  [C402H22]  94.92 84.98 180 bottom
C1111  SC1U10V2KX-1GP  [C402H22]  97.47 85.31 225 bottom
C1113  SC1U10V2KX-1GP  [C402H22]  102.04 87.99 225 bottom
C1114  SC22U6D3V3MX-1-GP  [C603H40]  101.09 87.2 225 bottom
C1115  SC1U10V2KX-1GP  [C402H22]  91.57 87.66 225 bottom
C1116  SC1U10V2KX-1GP  [C402H22]  115.33 97.97 270 bottom
C1118  SC1U10V2KX-1GP  [C402H22]  116.87 87.61 225 bottom
C1119  SC1U10V2KX-1GP  [C402H22]  115.92 86.27 225 bottom
C1120  SC22U6D3V3MX-1-GP  [C603H40]  114.55 41.66 0 bottom
C1121  SC1U10V2KX-1GP  [C402H22]  107.19 91.57 90 bottom
C1122  SC22U6D3V3MX-1-GP  [C603H40]  110.19 63.88 0 top
C1123  SC22U6D3V3MX-1-GP  [C603H40]  142.32 90.35 270 top
C1124  SC22U6D3V3MX-1-GP  [C603H40]  173.35 98.81 270 bottom
C1126  SC1U10V2KX-1GP  [C402H22]  91.57 90.37 225 top
C1127  SC1U10V2KX-1GP  [C402H22]  91.97 91.21 225 top
C1128  SC1U10V2KX-1GP  [C402H22]  115.09 108.31 270 bottom
C1130  SC22U6D3V3MX-1-GP  [C603H40]  109.64 94.13 45 bottom
C1132  SC1U10V2KX-1GP  [C402H22]  89.76 93.98 225 top
C1133  SC1U10V2KX-1GP  [C402H22]  92.28 88.24 225 bottom
C1134  SC1U10V2KX-1GP  [C402H22]  115.17 100.85 270 bottom
C1137  SC1U10V2KX-1GP  [C402H22]  115.13 110.09 270 bottom
C1138  SC1U10V2KX-1GP  [C402H22]  115.13 109.23 270 bottom
C1201  SC10U6D3V3MX-GP  [C603H38]  173.32 88.58 270 bottom
C1202  SC10U6D3V3MX-GP  [C603H38]  173.34 100.14 270 bottom
C1203  SC10U6D3V3MX-GP  [C603H38]  173.29 91.15 270 bottom
C1204  SC10U6D3V3MX-GP  [C603H38]  173.34 101.36 270 bottom
C1205  SC10U6D3V3MX-GP  [C603H38]  173.32 86.17 270 bottom
C1206  SC10U6D3V3MX-GP  [C603H38]  173.32 87.36 270 bottom
C1207  SC10U6D3V3MX-GP  [C603H38]  173.4 97.55 270 bottom
C1208  SC10U6D3V3MX-GP  [C603H38]  173.32 89.9 270 bottom
C1209  SC1U10V2KX-1GP  [C402H22]  114.05 82.38 225 bottom
C1210  SC1U10V2KX-1GP  [C402H22]  173.23 95.76 90 top
C1211  SC1U10V2KX-1GP  [C402H22]  173.23 97.66 90 top
C1212  SC1U10V2KX-1GP  [C402H22]  173.35 101.47 90 top
C1213  SC1U10V2KX-1GP  [C402H22]  173.35 91.19 90 top
C1214  SC1U10V2KX-1GP  [C402H22]  173.35 89.28 90 top
C1215  SC1U10V2KX-1GP  [C402H22]  115.23 82.98 225 bottom
C1216  SC1U10V2KX-1GP  [C402H22]  136.7 90.42 90 top
C1217  SCD1U16V2KX-3GP  [C402H22]  149.78 46.49 270 bottom
C1218  SCD1U16V2KX-3GP  [C402H22]  149.73 45.59 270 bottom
C1219  SC1U10V2KX-1GP  [C402H22]  162.56 58.78 0 bottom
C1220  SC1U10V2KX-1GP  [C402H22]  161.46 58.81 0 bottom
C1221  SC1U10V2KX-1GP  [C402H22]  160.54 58.79 0 bottom
C1222  SC1U10V2KX-1GP  [C402H22]  159.17 58.63 0 bottom
C1223  SC10U6D3V3MX-GP  [C603H38]  169.05 60.72 0 bottom
C1224  SC10U6D3V3MX-GP  [C603H38]  167.63 60.72 0 bottom
C1225  SCD1U16V2KX-3GP  [C402H22]  125.22 39.09 90 bottom
C1226  SCD1U16V2KX-3GP  [C402H22]  90.93 40.64 180 bottom
C1227  SC1KP50V2KX-1GP  [C402H22]  98.76 40.36 270 bottom
C1230  SC10U6D3V3MX-GP  [C603H38]  173.29 92.42 270 bottom
C1231  SC10U6D3V3MX-GP  [C603H38]  173.42 93.76 270 bottom
C1301  SC10U6D3V3MX-GP  [C603H38]  115.75 41.65 0 bottom
C1302  SC10U6D3V3MX-GP  [C603H38]  116.94 41.65 0 bottom
C1303  SC10U6D3V3MX-GP  [C603H38]  119.38 41.65 0 bottom
C1304  SC10U6D3V3MX-GP  [C603H38]  118.14 41.65 0 bottom
C1305  SC10U6D3V3MX-GP  [C603H38]  121.8 41.65 0 bottom
C1306  SC10U6D3V3MX-GP  [C603H38]  123.17 41.65 0 bottom
C1307  SC10U6D3V3MX-GP  [C603H38]  120.6 41.65 0 bottom
C1308  SC10U6D3V3MX-GP  [C603H38]  124.51 41.68 0 bottom
C1309  SC1U10V2KX-1GP  [C402H22]  109.35 41.68 0 bottom
C1310  SC1U10V2KX-1GP  [C402H22]  121.28 90.12 225 bottom
C1311  SC1U10V2KX-1GP  [C402H22]  108.23 41.71 0 bottom
C1312  SC1U10V2KX-1GP  [C402H22]  114.78 69.7 315 top
C1313  SC1U10V2KX-1GP  [C402H22]  110.34 41.68 0 bottom
C1314  SC1U10V2KX-1GP  [C402H22]  173.23 99.69 90 top
C1315  SCD1U16V2KX-3GP  [C402H22]  173.35 87.76 90 top
C1316  SC1U10V2KX-1GP  [C402H22]  120.67 89.49 225 bottom
C1317  SCD1U16V2KX-3GP  [C402H22]  169.7 57.04 180 bottom
C1318  SCD1U16V2KX-3GP  [C402H22]  170.64 57.06 180 bottom
C1319  SC1U10V2KX-1GP  [C402H22]  154.25 49.58 270 bottom
C1320  SC1U10V2KX-1GP  [C402H22]  154.25 48.46 270 bottom
C1321  SC1U10V2KX-1GP  [C402H22]  154.25 47.34 270 bottom
C1322  SC1U10V2KX-1GP  [C402H22]  154.25 46.23 270 bottom
C1323  SC10U6D3V3MX-GP  [C603H38]  153.87 44.96 270 bottom
C1324  SC10U6D3V3MX-GP  [C603H38]  153.87 43.53 270 bottom
C1325  SCD1U16V2KX-3GP  [C402H22]  174.37 81.41 0 bottom
C1326  SCD1U16V2KX-3GP  [C402H22]  164.06 127.23 270 bottom
C1327  SC1KP50V2KX-1GP  [C402H22]  168.78 126.24 90 bottom
C1330  SC10U6D3V3MX-GP  [C603H38]  173.39 96.32 270 bottom
C1331  SC10U6D3V3MX-GP  [C603H38]  173.39 95.07 270 bottom
C1412  SCD01U50V2KX-1GP  [C402H22]  56.47 23.04 0 top
C1413  SCD01U50V2KX-1GP  [C402H22]  57.36 23.04 0 top
C1417  SCD01U50V2KX-1GP  [C402H22]  53.02 23.04 0 top
C1418  SCD01U50V2KX-1GP  [C402H22]  53.93 23.04 0 top
C1419  SCD01U50V2KX-1GP  [C402H22]  65.41 23.01 0 top
C1420  SCD01U50V2KX-1GP  [C402H22]  62.37 23.01 0 top
C1421  SCD01U50V2KX-1GP  [C402H22]  63.25 23.01 0 top
C1422  SCD01U50V2KX-1GP  [C402H22]  64.52 23.01 0 top
C1501  SC6D8P50V2CN-GP  [C402H22]  97.55 101.42 135 top
C1502  SC6D8P50V2CN-GP  [C402H22]  96.55 99.06 315 top
C1801  SCD1U16V2KX-3GP  [C402H22]  52.58 88.9 90 top
C1802  SCD1U16V2KX-3GP  [C402H22]  52.58 89.79 90 top
C1803  SC22P50V2JN-4GP  [C402H22]  22.38 148.06 180 top
C1901  SCD1U16V2ZY-2GP  [C402H22]  7.19 121.87 90 top
C1902  SCD1U16V2ZY-2GP  [C402H22]  160.02 143.51 180 top
C1903  SCD1U16V2KX-3GP  [C402H22]  96.49 92.28 90 bottom
C1905  SCD1U16V2KX-3GP  [C402H22]  7.65 111.38 270 top
C1906  SCD1U16V2KX-3GP  [C402H22]  6.73 117.86 270 top
C1907  SCD1U16V2KX-3GP  [C402H22]  6.73 116.97 270 top
C1908  SCD1U16V2KX-3GP  [C402H22]  6.73 116.08 270 top
C1909  SCD1U16V2KX-3GP  [C402H22]  23.77 122.31 0 top
C1910  SCD1U16V2KX-3GP  [C402H22]  22.85 122.31 0 top
C1911  SCD1U16V2KX-3GP  [C402H22]  7.19 122.76 270 top
C1912  SCD1U16V2KX-3GP  [C402H22]  24.99 120.62 0 top
C1913  SCD1U16V2KX-3GP  [C402H22]  21.97 122.3 0 top
C2001  SC100P50V2JN-3GP  [C402H22]  111.51 20.7 90 bottom
C2002  SCD1U16V2KX-3GP  [C402H22]  96.06 25.08 90 bottom
C2003  SC1U10V2KX-1GP  [C402H22]  116.74 31.3 0 bottom
C2004  SC4D7U6D3V2MX-GP-U  [C402-TO0D2H26]  94.74 28.68 90 bottom
C2005  SC100P50V2JN-3GP  [C402H22]  100.78 33.17 180 bottom
C2006  SCD1U16V2KX-3GP  [C402H22]  96.06 24.19 90 bottom
C2008  SC1U10V2KX-1GP  [C402H22]  102.87 19.1 270 bottom
C2009  SCD1U16V2KX-3GP  [C402H22]  96.54 21.68 180 bottom
C2010  SC1U10V3ZY-6GP  [C603H36]  105.21 19 90 bottom
C2011  SCD1U16V2KX-3GP  [C402H22]  98.92 23.29 270 bottom
C2012  SCD1U16V2KX-3GP  [C402H22]  109.14 35.97 0 bottom
C2013  SCD1U16V2KX-3GP  [C402H22]  110.03 35.83 0 bottom
C2014  SCD1U16V2KX-3GP  [C402H22]  114.17 20.32 180 bottom
C2015  SCD1U16V2ZY-2GP  [C402H22]  110.89 35.83 180 bottom
C2016  SCD1U16V2KX-3GP  [C402H22]  99.69 21.36 90 bottom
C2017  SC1U10V2KX-1GP  [C402H22]  115.82 24.64 270 bottom
C2018  SCD1U16V2ZY-2GP  [C402H22]  115.31 31.83 90 bottom
C2019  SCD1U16V2KX-3GP  [C402H22]  103.38 20.6 180 bottom
C2020  SCD1U16V2KX-3GP  [C402H22]  104.32 20.58 180 bottom
C2040  SC1U10V2KX-1GP  [C402H22]  108.28 35.97 0 bottom
C2101  SCD1U16V2ZY-2GP  [C402H22]  47.8 112.72 270 top
C2102  SC4D7U6D3V2MX-GP-U  [C402-TO0D2H26]  52.45 114.2 270 top
C2103  SCD1U16V2KX-3GP  [C402H22]  52.46 115.18 270 top
C2104  SCD1U16V2KX-3GP  [C402H22]  56.32 124.07 270 bottom
C2105  SCD1U16V2KX-3GP  [C402H22]  42.47 121.34 0 top
C2106  SC4D7U6D3V2MX-GP-U  [C402-TO0D2H26]  60.45 115.95 90 top
C2107  SCD1U16V2KX-3GP  [C402H22]  51.76 117.51 0 bottom
C2108  SCD1U16V2KX-3GP  [C402H22]  50.88 117.5 0 bottom
C2109  SCD1U16V2KX-3GP  [C402H22]  50.69 122.09 180 bottom
C2110  SCD1U16V2KX-3GP  [C402H22]  51.57 122.09 180 bottom
C2111  SCD1U16V2KX-3GP  [C402H22]  53.71 120.07 90 bottom
C2114  SC1U10V2KX-1GP  [C402H22]  52.66 117.51 0 bottom
C2115  SCD1U16V2KX-3GP  [C402H22]  60.48 115.02 90 top
C2116  SC15P50V2JN-2-GP  [C402H22]  58.22 120.41 0 top
C2117  SC15P50V2JN-2-GP  [C402H22]  58.22 118.41 180 top
C2119  SC4D7U6D3V3KX-GP  [C603H36]  46.82 122.25 180 top
C2120  SC4D7U6D3V3KX-GP  [C603H36]  57.56 123.13 90 top
C2201  SCD1U16V2KX-3GP  [C402H22]  10.29 131.19 180 top
C2202  SC10U10V5ZY-1GP  [C805H54]  11.4 159.57 0 top
C2203  SCD1U16V2KX-3GP  [C402H22]  12.85 158.96 0 top
C2204  SC10U10V5ZY-1GP  [C805H54]  22.56 165.46 180 top
C2205  SCD1U16V2KX-3GP  [C402H22]  22.08 163.23 270 top
C2206  SC22P50V2JN-4GP  [C402H22]  19.34 148.05 0 top
C2207  SCD1U16V2KX-3GP  [C402H22]  21.26 150.37 90 top
C2208  SCD1U16V2KX-3GP  [C402H22]  14.5 149.04 0 top
C2209  SC10U10V5KX-2GP  [C805H54]  15.92 148.38 0 top
C2210  SC4D7P50V2CN-1GP  [C402H22]  19.84 146.64 270 top
C2211  SCD1U16V2KX-3GP  [C402H22]  17.4 163.32 270 top
C2212  SC10U10V5KX-2GP  [C805H54]  17.27 165.74 180 top
C2215  SCD1U16V2KX-3GP  [C402H22]  33.78 142.88 180 top
C2216  SCD1U16V2KX-3GP  [C402H22]  26.77 145.07 180 top
C2217  SCD1U16V2KX-3GP  [C402H22]  41.36 139.15 135 top
C2218  SC10U10V5KX-2GP  [C805H54]  20.63 165.46 180 top
C2219  SCD1U16V2KX-3GP  [C402H22]  20.15 163.23 270 top
C2220  SC10U10V5KX-2GP  [C805H54]  17.88 148.37 0 top
C2227  SC100P50V2JN-3GP  [C402H22]  10.01 133.62 0 top
C2228  SC100P50V2JN-3GP  [C402H22]  9.94 135.7 0 top
C2229  SC1KP50V2KX-1GP  [C402H22]  11.44 131.25 0 top
C2230  SC100P50V2JN-3GP  [C402H22]  9.96 137.65 180 top
C2231  SC100P50V2JN-3GP  [C402H22]  9.96 139.6 180 top
C2301  SCD1U16V2KX-3GP  [C402H22]  157.48 160.02 180 top
C2303  SC470P50V2KX-3GP  [C402H22]  160.02 145.41 180 top
C2415  SCD1U16V2KX-3GP  [C402H22]  164.59 155.85 270 bottom
C2434  SCD1U16V2KX-3GP  [C402H22]  120.5 34.65 90 bottom
C2435  SCD1U16V2KX-3GP  [C402H22]  113.87 35.92 0 bottom
C2501  SCD1U16V2KX-3GP  [C402H22]  188.93 37.08 180 top
C2503  SC1U10V2KX-1GP  [C402H22]  193.29 52.7 180 top
C2506  SC10U6D3V3MX-GP  [C603H38]  78.23 46.99 270 bottom
C2507  SCD1U16V2KX-3GP  [C402H22]  77.85 45.97 90 bottom
C2701  SC100P50V2JN-3GP  [C402H22]  50.42 147.7 180 top
C2702  SC100P50V2JN-3GP  [C402H22]  57.28 147.45 180 top
C2703  SC100P50V2JN-3GP  [C402H22]  52.45 147.7 180 top
C2704  SC100P50V2JN-3GP  [C402H22]  45.47 147.45 180 top
C2705  SC100P50V2JN-3GP  [C402H22]  44.14 149.04 0 top
C2706  SC100P50V2JN-3GP  [C402H22]  39.81 151.68 180 top
C2707  SC22U6D3V3MX-1-GP  [C603H40]  17.13 141.86 270 top
C2708  SCD1U16V2ZY-2GP  [C402H22]  19.08 141.61 0 top
C2709  SCD1U16V2KX-3GP  [C402H22]  23.5 138.59 180 top
C2809  SCD1U16V2ZY-2GP  [C402H22]  60.1 145.69 270 top
C2810  SCD1U16V2ZY-2GP  [C402H22]  61.19 141.64 0 top
C2811  SCD1U16V2ZY-2GP  [C402H22]  86.71 141.69 0 top
C2813  SCD1U16V2KX-3GP  [C402H22]  60.23 147.29 0 top
C2903  SCD1U16V2ZY-2GP  [C402H22]  61.14 147.28 0 top
C2907  SC1KP50V2KX-1GP  [C402H22]  101.42 146.94 0 top
C2908  SC1KP50V2KX-1GP  [C402H22]  19.48 11.94 0 top
C2911  SCD1U16V2ZY-2GP  [C402H22]  18.06 11.4 90 top
C2912  SC1U10V2KX-1GP  [C402H22]  21.44 32.18 270 top
C3301  SC1KP50V2KX-1GP  [C402H22]  103.63 136.78 0 top
C3302  SC1KP50V2KX-1GP  [C402H22]  104.52 136.78 0 top
C3402  SCD1U16V2KX-3GP  [C402H22]  176.15 21.54 270 top
C3403  SC1KP50V2KX-1GP  [C402H22]  16.31 26.47 0 bottom
C3404  SC4D7U6D3V2MX-GP-U  [C402-TO0D2H26]  31.62 15.14 270 top
C3405  SCD1U16V2KX-3GP  [C402H22]  31.67 16.08 270 top
C3406  SCD01U25V2KX-3GP  [C402H22]  31.65 16.99 270 top
C3407  SCD1U16V2KX-3GP  [C402H22]  165.99 15.77 0 bottom
C3408  SCD1U16V2KX-3GP  [C402H22]  154.51 21.44 0 bottom
C3410  SCD1U16V2KX-3GP  [C402H22]  30.81 18.65 180 top
C3411  SCD1U16V2ZY-2GP  [C402H22]  114.8 18.85 90 bottom
C3416  SCD1U16V2ZY-2GP  [C402H22]  17.42 21.39 270 bottom
C3501  SCD1U16V2KX-3GP  [C402H22]  8.64 93.34 180 bottom
C3502  SC1U10V2KX-1GP  [C402H22]  7.82 95.81 90 bottom
C3504  SC1U10V3ZY-6GP  [C603H36]  181.51 18.54 180 top
C3505  SC1U10V2KX-1GP  [C402H22]  7.44 94.77 270 bottom
C3506  SC1U10V3ZY-6GP  [C603H36]  181.53 21.21 180 top
C3507  SC1U10V3ZY-6GP  [C603H36]  187.53 25.12 90 top
C3508  SCD1U16V2KX-3GP  [C402H22]  179.6 14.07 180 top
C3509  SCD1U16V2KX-3GP  [C402H22]  186.72 19.43 180 top
C4301  SCD1U25V3KX-GP  [C603H36]  181.18 92.47 180 bottom
C4302  SCD1U50V3KX-GP  [C603H36]  169.39 16.51 180 top
C4303  SCD01U50V2KX-1GP  [C402H22]  170.9 14.27 270 top
C4601  SCD1U16V2KX-3GP  [C402H22]  36.69 107.75 270 bottom
C4602  SC1U10V2KX-1GP  [C402H22]  37.85 101.83 180 bottom
C4603  SC12P50V2JN-3GP  [C402H24]  45.01 96.7 180 top
C4604  SC12P50V2JN-3GP  [C402H24]  45.01 98.65 0 top
C4605  SCD1U16V2KX-3GP  [C402H22]  47.19 104.75 270 bottom
C4606  SCD1U16V2KX-3GP  [C402H22]  40.51 96.08 180 bottom
C4607  SC1U10V2KX-1GP  [C402H22]  39.62 96.08 180 bottom
C4608  SCD1U16V2KX-3GP  [C402H22]  43.26 95.95 180 bottom
C4609  SC1U10V2KX-1GP  [C402H22]  44.15 95.95 180 bottom
C4610  SCD1U16V2KX-3GP  [C402H22]  49.33 102.23 270 bottom
C4611  SCD1U16V3KX-3GP  [C603H36]  36.32 108.81 90 bottom
C5001  SCD1U50V3KX-GP  [C603H36]  81.43 13.18 0 top
C5301  SC4D7P50V2BN-GP  [C402H22]  171.4 155.75 90 top
C5303  SC100P50V2JN-3GP  [C402H22]  184.23 160.4 180 top
C5304  SC18P50V2JN-1-GP  [C402H22]  180.21 153.54 270 top
C5305  SC18P50V2JN-1-GP  [C402H22]  180.21 151.51 270 top
C5306  SC100P50V2JN-3GP  [C402H22]  179.22 160.4 180 top
C5307  SC4D7P50V2BN-GP  [C402H22]  173.43 155.75 90 top
C5308  SC4D7P50V2BN-GP  [C402H22]  175.39 155.75 90 top
C5309  SC4D7P50V2BN-GP  [C402H22]  171.4 159.31 90 top
C5310  SC4D7P50V2BN-GP  [C402H22]  173.43 159.31 90 top
C5311  SC4D7P50V2BN-GP  [C402H22]  175.39 159.31 90 top
C5401  SCD1U16V2KX-3GP  [C402H22]  147.04 145.95 180 top
C5402  SCD1U16V2KX-3GP  [C402H22]  148.06 145.95 180 top
C5403  SCD1U16V2KX-3GP  [C402H22]  143.26 146.18 180 top
C5404  SCD1U16V2KX-3GP  [C402H22]  144.27 146.18 180 top
C5405  SCD1U16V2KX-3GP  [C402H22]  140.23 146.02 180 top
C5406  SCD1U16V2KX-3GP  [C402H22]  141.25 146.02 180 top
C5407  SCD1U16V2KX-3GP  [C402H22]  150.14 145.72 180 top
C5408  SCD1U16V2KX-3GP  [C402H22]  151.28 145.75 180 top
C5409  SCD1U16V2KX-3GP  [C402H22]  157.72 17.4 90 top
C5410  SCD1U16V2KX-3GP  [C402H22]  157.44 22.38 90 top
C5411  SCD1U50V3KX-GP  [C603H36]  162.53 18.53 0 top
C5412  SC1KP50V2KX-L-1-GP  [C402H22]  155.28 20.12 270 top
C5413  SC22U6D3V3MX-1-GP  [C603H40]  161.93 21.44 90 top
C5414  SC1KP50V2KX-L-1-GP  [C402H22]  155.7 17.77 0 top
C5415  SC22U6D3V3MX-1-GP  [C603H40]  154.97 21.92 0 top
C5416  SC1U10V2KX-1GP  [C402H22]  159.65 17.37 270 top
C5417  SC22U6D3V3MX-1-GP  [C603H40]  122.17 21.72 270 bottom
C5418  SC1U10V2KX-1GP  [C402H22]  159.4 22.35 270 top
C5419  SC22U6D3V3MX-1-GP  [C603H40]  158.32 16.26 90 top
C5601  SCD1U16V2ZY-2GP  [C402H22]  155.01 156.51 270 bottom
C5602  SCD1U16V2ZY-2GP  [C402H22]  155.01 155.52 270 bottom
C5603  SCD1U16V2ZY-2GP  [C402H22]  132.01 154.84 90 bottom
C5604  SCD1U16V2ZY-2GP  [C402H22]  132.01 155.83 90 bottom
C6001  SCD1U25V3KX-GP  [C603H36]  30.71 37.67 180 top
C6002  SCD1U25V3KX-GP  [C603H36]  30.73 52.32 180 top
C6003  SC10U25V5KX-GP  [C805H56]  29.03 37.79 0 top
C6004  SC10U25V5KX-GP  [C805H56]  29.11 52.32 0 top
C6101  SCD1U25V2KX-2-GP  [C402H22]  24.75 68.4 270 top
C6102  SC10U6D3V3MX-GP  [C603H38]  24.27 56.41 0 top
C6103  SCD1U25V2KX-2-GP  [C402H22]  23.19 56.12 0 top
C6104  SCD1U25V2KX-2-GP  [C402H22]  46.89 65.44 0 top
C6105  SC10P50V2JN-4GP  [C402H22]  29.84 74.42 180 top
C7537  SC1U10V2KX-L1-GP  [C402H22]  34.09 134.9 0 bottom
C7538  SC7P50V2DN-2GP  [C402H22]  93.43 95.3 135 top
C7539  SC1U10V2KX-L1-GP  [C402H22]  53.7 110.24 270 bottom
C7540  SC7P50V2DN-2GP  [C402H22]  92.06 93.94 315 top
C7542  SCD1U16V2KX-3GP  [C402H22]  96.22 77.17 135 top
C7924  SCD1U25V2KX-GP  [C402H22]  97.03 34.8 180 bottom
C9602  SCD1U16V2KX-3GP  [C402H22]  191.29 105.26 180 bottom
C9603  SCD1U16V2KX-3GP  [C402H22]  177.41 107.04 90 bottom
C9604  SCD1U16V2KX-3GP  [C402H22]  190.37 109.58 270 bottom
C9605  SCD1U10V2KX-5GP  [C402H22]  178.61 97.05 0 bottom
C9606  SCD1U16V2KX-3GP  [C402H22]  177.93 108.97 270 bottom
C15110  SCD1U16V2KX-3GP  [C402H22]  31.57 127.94 180 top
C15111  SC1U10V2KX-1GP  [C402H22]  32.46 127.94 180 top
C15112  SCD1U16V2KX-3GP  [C402H22]  54.48 86.36 90 top
C15113  SCD1U16V2KX-3GP  [C402H22]  54.48 87.25 90 top
C15114  SCD1U16V2KX-3GP  [C402H22]  65.66 83.44 90 top
C15115  SCD1U16V2KX-3GP  [C402H22]  65.66 82.55 90 top
C15116  SCD1U16V2KX-3GP  [C402H22]  44.69 116.52 270 top
C15117  SCD1U16V2KX-3GP  [C402H22]  44.7 117.42 270 top
C15118  SCD1U16V2KX-3GP  [C402H22]  47.22 115.6 270 top
C15119  SCD1U16V2KX-3GP  [C402H22]  47.22 114.71 270 top
C15120  SCD1U16V2KX-3GP  [C402H22]  81.61 135.47 180 top
C15121  SCD1U16V2KX-3GP  [C402H22]  82.6 135.47 180 top
C15122  SCD1U16V2KX-3GP  [C402H22]  84.18 135.39 180 top
C15123  SCD1U16V2KX-3GP  [C402H22]  85.14 135.39 180 top
C15124  SCD1U16V2KX-3GP  [C402H22]  55.75 34.37 270 top
C15125  SCD1U16V2KX-3GP  [C402H22]  55.75 35.26 270 top
C15126  SCD1U16V2KX-3GP  [C402H22]  55.58 40.16 270 top
C15127  SCD1U16V2KX-3GP  [C402H22]  55.58 39.27 270 top
C15129  SCD1U16V2ZY-2GP  [C402H22]  8.41 111.4 180 bottom
C15141  SCD1U16V2KX-3GP  [C402H22]  174.09 142.49 180 top
C15142  SCD1U16V2KX-3GP  [C402H22]  174.98 142.49 180 top
C15143  SCD1U16V2KX-3GP  [C402H22]  175.9 142.49 180 top
C15144  SCD1U16V2KX-3GP  [C402H22]  176.78 142.49 180 top
C15145  SCD1U16V2KX-3GP  [C402H22]  171.04 142.49 180 top
C15146  SCD1U16V2KX-3GP  [C402H22]  171.93 142.49 180 top
C15147  SC10U6D3V3MX-GP  [C603H38]  169.8 145.48 0 top
C15148  SC10U6D3V3MX-GP  [C603H38]  178.29 157.57 90 top
C15149  SCD1U16V2KX-3GP  [C402H22]  169.04 152.27 0 top
C15150  SCD1U16V2KX-3GP  [C402H22]  176.53 148.97 270 bottom
C15151  SCD1U16V2KX-3GP  [C402H22]  171.96 150.5 90 bottom
C15152  SCD1U16V2KX-3GP  [C402H22]  173.71 147.19 180 bottom
C15153  SC2D2U10V3KX-1GP  [C603H36]  172.64 147.4 180 bottom
C15154  SCD1U16V2KX-3GP  [C402H22]  170.84 145.26 180 top
C15155  SCD1U16V2KX-3GP  [C402H22]  178.23 155.24 270 top
C15156  SC2D2U10V3KX-1GP  [C603H36]  178.29 156.35 270 top
C15157  SCD1U16V2KX-3GP  [C402H22]  163.96 159.49 180 top
C15163  SCD1U16V2KX-3GP  [C402H22]  121.49 146.05 180 top
C15164  SCD1U16V2KX-3GP  [C402H22]  122.5 146.05 180 top
C15165  SCD1U16V2KX-3GP  [C402H22]  118.9 146.35 180 top
C15166  SCD1U16V2KX-3GP  [C402H22]  119.91 146.35 180 top
C15167  SCD1U16V2KX-3GP  [C402H22]  114.96 145.72 180 top
C15170  SCD1U16V2KX-3GP  [C402H22]  115.98 145.72 180 top
C15171  SCD1U16V2KX-3GP  [C402H22]  111.18 145.08 180 top
C15172  SCD1U16V2KX-3GP  [C402H22]  112.19 145.08 180 top
C15173  SCD1U16V2KX-3GP  [C402H22]  133.05 157.35 0 top
C15174  SCD1U16V2KX-3GP  [C402H22]  63.64 127.55 270 bottom
C15175  SCD1U16V2KX-3GP  [C402H22]  69.94 129.43 180 top
C15178  SCD1U10V2KX-4GP  [C402H20]  94.39 92.08 0 bottom
C15183  SCD1U16V2ZY-2GP  [C402H22]  25.5 27.94 90 top
C15184  SCD1U16V2ZY-2GP  [C402H22]  122.81 157.23 0 bottom
C15185  SC1U10V2KX-1GP  [C402H22]  126.9 150.16 90 bottom
C15186  SCD1U16V2KX-3GP  [C402H22]  4.57 122.43 0 bottom
C15187  SC1U10V2KX-1GP  [C402H22]  6.32 124.79 270 bottom
C15188  SCD1U16V2KX-3GP  [C402H22]  8.26 125.02 90 bottom
C15189  SC1U10V2KX-1GP  [C402H22]  115.21 90.35 90 bottom
C15190  SC1U10V2KX-1GP  [C402H22]  118.66 91.48 315 bottom
C15191  SCD1U16V2KX-3GP  [C402H22]  116.99 154.03 270 top
C15192  SCD1U16V2KX-3GP  [C402H22]  13.69 13.23 0 top
CMOS1  PIN-CON3-S-GP  [21S-91-03GB01]  36.24 125.82 90 top
CPU1  BRASWELL-GP  [BGA1170M2725H57]  113.9 89.96 225 top
D3  BAW56-5-GP  [SOT-23-9H44]  165.53 153.39 180 bottom
D4  BAW56-5-GP  [SOT-23-9H44]  130.68 152.27 0 bottom
D1501  BAT54C-11-GP  [SOT23-2D4-312H44]  32.38 124.94 0 top
D2101  1SS355GP-GP  [SOD323AKH40]  43.98 119.99 180 top
D2201  BAT54A-3-GP  [SOT-23-10H44]  17.33 134.6 270 top
D2202  DF2B6D8E-GP  [D1608AK-UH28]  6.51 126.58 270 top
D2203  BAT54A-3-GP  [SOT-23-10H44]  17.34 138.18 270 top
D2402  1SS355GP-GP  [SOD323AKH40]  165.61 154.31 90 top
D2502  1SS355GP-GP  [SOD323AKH40]  194.82 51.54 180 top
D2701  DF2B6D8E-GP  [D1608AK-UH28]  56.85 146.02 180 bottom
D2702  DF2B6D8E-GP  [D1608AK-UH28]  54.26 146.03 180 bottom
D2703  DF2B6D8E-GP  [D1608AK-UH28]  55.53 146.03 180 bottom
D2704  AZ5125-02S-R7G-GP  [SOT23-2D4-312H46]  54.86 146.61 180 top
D2705  AZ5125-02S-R7G-GP  [SOT23-2D4-312H46]  47.88 146.43 180 top
D2706  AZ5125-02S-R7G-GP  [SOT23-2D4-312H46]  42.29 152.26 90 top
D3401  1SS355GP-GP  [SOD323AKH40]  7.06 37.36 180 bottom
D3402  BAT54A-7-F-2-GP  [SOT23-2D4-312H48]  6.63 45.39 270 bottom
D3403  BAT54A-7-F-2-GP  [SOT23-2D4-312H48]  6.5 49.45 270 bottom
D3404  BAT54A-7-F-2-GP  [SOT23-2D4-312H48]  6.6 41.4 270 bottom
DBGH1  PIN-CONN14A-SFP1-GP  [220-47-07GB22]  68.22 48.13 90 top
DCIN1  DC-JACK200-GP-U  [2DC-G726-Q15]  190.3 166.4 180 top
DIMM1  DDR3-204P-104-GP  [AAA-DDR-109-P06]  165 91.5 270 top
DIMM2  DDR3-204P-234-GP  [1932208-1]  119.01 46.69 180 top
DIMM3  DDR3-204P-42-GP  [1932210-1]  119.01 46.69 180 top
EC2314  SC100P50V2JN-3GP  [C402H22]  153.11 152.4 0 top
EC2323  SC100P50V2JN-3GP  [C402H22]  157.91 153.57 180 top
EC2501  SC4D7P50V2CN-1GP  [C402H22]  78.56 59.89 90 top
EC2502  SC4D7P50V2CN-1GP  [C402H22]  75.62 44.3 0 top
EC2503  SC4D7P50V2CN-1GP  [C402H22]  74.52 44.32 0 top
EC2801  SC1D5P50V2CN-1GP  [C402H22]  47.45 124.26 270 top
EC2802  SC1D5P50V2CN-1GP  [C402H22]  58.03 125.18 270 top
EC2803  SC1D5P50V2CN-1GP  [C402H22]  50.3 125.21 270 top
EC2804  SC1D5P50V2CN-1GP  [C402H22]  60.06 125.21 90 top
EC2805  SC1D5P50V2CN-1GP  [C402H22]  52.25 125.18 90 top
EC2806  SC1D5P50V2CN-1GP  [C402H22]  54.19 125.18 270 top
EC2807  SC1D5P50V2CN-1GP  [C402H22]  56.1 125.18 90 top
EC2808  SC1D5P50V2CN-1GP  [C402H22]  49.35 124.23 90 top
EC3401  SCD1U16V2KX-3GP  [C402H22]  187.55 26.16 270 top
EC3409  SCD1U16V2ZY-2GP  [C402H22]  143.87 14.16 0 top
EC3412  SCD1U16V2KX-3GP  [C402H22]  178.13 13.67 270 top
EC3413  SCD1U16V2KX-3GP  [C402H22]  150.77 40.54 270 bottom
EC3414  SCD1U16V2KX-3GP  [C402H22]  114.3 14.1 270 bottom
EC4101  SCD1U50V3KX-GP  [C603H36]  185.78 150.89 180 top
EC4102  SCD1U25V2KX-GP  [C402H22]  186.84 151.12 0 top
EC7612  SC100P50V2JN-3GP  [C402H22]  131.34 155.22 180 top
EC7613  SC100P50V2JN-3GP  [C402H22]  124.87 152.58 0 top
EC7615  SC22P50V2JN-4GP  [C402H22]  94.72 82.47 270 top
EC7616  SC22P50V2JN-4GP  [C402H22]  90.35 82.4 90 top
EC7617  SC22P50V2JN-4GP  [C402H22]  90.35 83.29 90 top
ED2  AZC099-04S-1-GP  [SOT-6H58]  181.69 159 180 top
ED2301  AZ1045-04F-R7G-GP  [DFN10G2510H26]  141.99 154.94 180 top
ED2302  AZ1045-04F-R7G-GP  [DFN10G2510H26]  149.08 155.02 180 top
ED2303  AZC099-04S-1-GP  [SOT-6H58]  154.05 155.57 270 top
ED2304  AZC099-04S-1-GP  [SOT-6H58]  127.1 155.66 270 top
ED2305  AZ1045-04F-R7G-GP  [DFN10G2510H26]  121.62 154.69 180 top
ED2306  AZ1045-04F-R7G-GP  [DFN10G2510H26]  113.56 154.76 180 top
ED2307  AZ1045-04F-R7G-GP  [DFN10G2510H26]  63.73 141.62 0 top
ED2308  AZ1045-04F-R7G-GP  [DFN10G2510H26]  83.16 141.29 0 top
ED2801  AZC099-04S-1-GP  [SOT-6H58]  78.53 140.57 0 top
ED2802  AZC099-04S-1-GP  [SOT-6H58]  69.34 140.59 0 top
ED2804  AZC099-04S-1-GP  [SOT-6H58]  73.79 140.59 0 top
ED2907  AZC099-04S-1-GP  [SOT-6H58]  47.1 20.07 90 top
ED3201  AZ5725-01FDR7G-GP  [SOD882-10D6-1H20]  96.11 149.76 270 top
ED3202  AZ5725-01FDR7G-GP  [SOD882-10D6-1H20]  24.1 119.96 0 top
ED3203  AZC099-04S-1-GP  [SOT-6H58]  58.85 138.67 90 top
ED4101  P6SBMJ24APT-GP  [D5436AKH97]  189.11 154.57 90 top
ED6512  AZC099-04S-1-GP  [SOT-6H58]  49.12 43.03 90 top
ED6513  AZ1045-04F-R7G-GP  [DFN10G2510H26]  47.96 33.68 90 top
ED6514  AZ1045-04F-R7G-GP  [DFN10G2510H26]  47.9 38.25 90 top
ED6520  AZC099-04S-1-GP  [SOT-6H58]  166.75 158.98 90 top
ED6521  AZC099-04S-1-GP  [SOT-6H58]  99.01 147.9 0 top
EL5314  FILTER-4P-98-GP  [L125100-4P-5H24]  82.11 138 180 top
EL5316  COIL-90OHM-100MHZ-5-GP  [L125100-4P-4H24]  72.77 135.76 90 top
EL5317  COIL-90OHM-100MHZ-5-GP  [L125100-4P-4H24]  70.43 136 90 top
EL5318  COIL-90OHM-100MHZ-5-GP  [L125100-4P-4H24]  67.94 136.02 90 top
EL5321  COIL-90OHM-100MHZ-5-GP  [L125100-4P-4H24]  42.96 19.63 0 top
EL5322  COIL-90OHM-100MHZ-5-GP  [L125100-4P-4H24]  77.37 136.5 90 top
EL5323  COIL-90OHM-100MHZ-5-GP  [L125100-4P-4H24]  79.65 136.5 90 top
EL5324  FILTER-4P-98-GP  [L125100-4P-5H24]  64.84 138.51 180 top
EL5325  FILTER-4P-98-GP  [L125100-4P-5H24]  84.4 138 180 top
EL5326  FILTER-4P-98-GP  [L125100-4P-5H24]  62.56 138.51 180 top
EL5327  COIL-90OHM-100MHZ-5-GP  [L125100-4P-4H24]  53.82 41.71 180 top
EL5328  FILTER-4P-98-GP  [L125100-4P-5H24]  51.49 34.8 270 top
EL5329  COIL-90OHM-100MHZ-5-GP  [L125100-4P-4H24]  53.82 44.09 180 top
EL5330  FILTER-4P-98-GP  [L125100-4P-5H24]  51.49 32.59 270 top
EL5331  FILTER-4P-98-GP  [L125100-4P-5H24]  51.46 39.24 270 top
EL5332  FILTER-4P-98-GP  [L125100-4P-5H24]  51.46 37.03 270 top
EL5333  FILTER-4P-98-GP  [L125100-4P-5H24]  59 29.51 0 top
EL5334  FILTER-4P-98-GP  [L125100-4P-5H24]  55.55 29.57 0 top
EL5335  FILTER-4P-98-GP  [L125100-4P-5H24]  66.34 29.31 0 top
EL5336  FILTER-4P-98-GP  [L125100-4P-5H24]  63.4 29.36 0 top
EL5337  COIL-90OHM-100MHZ-5-GP  [L125100-4P-4H24]  74.93 135.76 90 top
EL5601  FILTER-4P-120-GP  [L125100-4P-1H28]  139.88 151.76 90 top
EL5602  FILTER-4P-120-GP  [L125100-4P-1H28]  143.71 151.71 90 top
EL5603  FILTER-4P-120-GP  [L125100-4P-1H28]  147.5 151.76 90 top
EL5604  FILTER-4P-120-GP  [L125100-4P-1H28]  151.23 151.87 90 top
EL5605  FILTER-4P-120-GP  [L125100-4P-1H28]  111.68 151.51 90 top
EL5606  FILTER-4P-120-GP  [L125100-4P-1H28]  115.49 151.49 90 top
EL5607  FILTER-4P-120-GP  [L125100-4P-1H28]  119.43 151.51 90 top
EL5608  FILTER-4P-120-GP  [L125100-4P-1H28]  123.19 151.51 90 top
EL5609  COIL-90OHM-100MHZ-5-GP  [L125100-4P-4H24]  97.87 143.81 90 top
EL5610  COIL-90OHM-100MHZ-5-GP  [L125100-4P-4H24]  100.15 143.81 90 top
F2301  POLYSW-1D1A6V-9-GP-U  [POLYSW-2114H30]  160.15 155.7 0 bottom
F2402  POLYSW-1D1A6V-9-GP-U  [POLYSW-2114H30]  162.43 155.7 180 bottom
FANC1  JWT-CON3-S2-GP  [A2543WV2-3P]  193.31 42.39 270 top
FANC2  FOX-CON4-11-GP  [HF1004E]  193.31 43.66 270 top
G1  0R0402-PAD-2-GP  [0R0402-PAD-1]  94.04 20.96 90 bottom
G1901  GAP-OPEN  [CON2O-U]  53.34 108.97 90 bottom
G1902  GAP-OPEN  [CON2O-U]  32.72 134.9 180 bottom
GPIO1  JOWLE-CON2-5-GP  [A2541WV0-1EX2PA-6T]  71.46 24.32 270 top
GPIO2  JOWLE-CON2-5-GP  [A2541WV0-1EX2PA-6T]  75.06 24.33 270 top
H3301  GENS315R158-8-F-A-GP  [GENS315R158-8-F-A]  193.65 4.9 0 top
H3302  GENS315R158-8-F-A-GP  [GENS315R158-8-F-A]  36.17 4.9 0 top
H3303  GENS315R158-8-F-A-GP  [GENS315R158-8-F-A]  193.65 136.98 0 top
H3304  GENS315R158-8-F-A-GP  [GENS315R158-8-F-A]  36.17 159.84 0 top
HDMI1  SKT-HDMI23-47-GP  [SKT-HDMI23-150122-9]  143.23 160.44 180 top
HDMI2  SKT-HDMI23-47-GP  [SKT-HDMI23-150122-9]  120.95 160.44 180 top
HNGFF1  STF256R109H99-GP  [STF256R109H99]  35 92.57 0 top
L2101  IND-4D7UH-300-GP-U  [L3030-3009-2H40]  56.79 115.24 90 top
L2202  MHC1608S601LBP-GP  [L603H38]  5.18 128.6 0 top
L2701  0R0603-PAD-2-GP-U  [0R0603-PAD-1-U]  38.7 151.47 0 top
L2702  0R0603-PAD-2-GP-U  [0R0603-PAD-1-U]  52.2 145.29 180 top
L2703  0R0603-PAD-2-GP-U  [0R0603-PAD-1-U]  57.51 144.75 180 top
L2704  0R0603-PAD-2-GP-U  [0R0603-PAD-1-U]  44.35 145.82 180 top
L2705  0R0603-PAD-2-GP-U  [0R0603-PAD-1-U]  50.67 145.29 180 top
L2706  0R0603-PAD-2-GP-U  [0R0603-PAD-1-U]  43.03 148.76 180 top
L3401  MHC1608S601LBP-GP  [L603H38]  16.84 19.46 0 bottom
L5301  FCM1608CF-470T06-1-GP  [L603H38]  171.02 157.53 180 top
L5302  FCM1608CF-470T06-1-GP  [L603H38]  173.05 157.53 180 top
L5303  FCM1608CF-470T06-1-GP  [L603H38]  175.01 157.53 180 top
L5305  MHC1608S601LBP-GP  [L603H38]  36.37 106.6 90 bottom
L5311  MHC1608S601LBP-GP  [L603H38]  168.63 145.49 180 top
L5312  MHC1608S601LBP-GP  [L603H38]  178.28 158.85 90 top
L5313  MHC1608S601LBP-GP  [L603H38]  14.48 26.16 270 bottom
LAN1  RTL8111G-CGT-1-GP-U2  [QFN32J4-G2D85H36]  51.52 119.72 0 top
LEDH1  TCN-CONN14A-SFP-GP-U  [T11-0063-1A40-0-U]  24.5 17.6 90 top
NGFFE1  SKT-NGFF75P-91-GP  [AS0BC21-S40BE-7H]  35 64.32 180 top
NOREF  -  []  -50.83 -198.76 0 top
NOREF#2  -  []  0 0 0 top
NOREF#3  *  [unnamed#2]  184.5 141.59 0 top
NOREF#4  *  [unnamed#2]  5.58 164.44 0 top
NOREF#5  -  []  122.56 73.96 0 top
NOREF#6  -  []  143.51 107.82 0 top
NOREF#7  -  [unnamed#2]  86.01 67.16 18 top
NOREF#8  -  []  133.86 98.55 0 top
NOREF#9  -  []  0 0 0 top
NOREF#10  -  []  17.14 -131.87 180 top
NOREF#11  -  []  0 0 0 top
NOREF#12  *  [unnamed#2]  188.52 10.54 0 top
NOREF#13  -  [unnamed#2]  141.79 112.76 0 top
NOREF#14  *  [unnamed#2]  24.42 4.53 0 top
NOREF#15  -  []  165 124.9 0 top
NOREF#16  -  []  152.43 90.17 90 top
NOREF#17  -  []  182.86 131.87 0 top
NOREF#18  *  [unnamed#2]  102.11 122.3 0 top
NOREF#19  -  []  5.84 69.93 90 top
NOREF#20  *  [unnamed#2]  111.89 60.33 0 top
NOREF#21  *  [unnamed#2]  5.58 164.44 180 bottom
NOREF#22  *  [unnamed#2]  5.81 11.53 180 bottom
NOREF#23  *  [unnamed#2]  194.38 150.93 180 bottom
NOREF#24  *  [unnamed#2]  185.92 2.97 180 bottom
NOREF#25  *  [unnamed#2]  146.53 23.55 180 bottom
NOREF#26  *  [unnamed#2]  87.88 42.14 180 bottom
OSC1  OSC-48MHZ-16GP  [SMD-OSC8H52]  121 28.86 270 bottom
PC3601  SC10U10V5ZY-1GP  [C805H54]  114.48 16.41 90 bottom
PC3602  SCD1U16V2KX-3GP  [C402H22]  114.81 14.99 90 bottom
PC3603  SC10U10V5ZY-1GP  [C805H54]  124.28 4.88 90 top
PC3604  E220U16VM-25-GP  [ECAP-100D6D3H473]  118.08 5.51 0 top
PC4201  SCD1U25V3KX-GP  [C603H36]  182.6 70.17 180 bottom
PC4202  SCD1U16V2KX-3GP  [C402H22]  186.81 91.26 270 bottom
PC4203  SCD1U16V2KX-3GP  [C402H22]  184.8 93.29 90 bottom
PC4204  SCD1U50V3KX-GP  [C603H36]  188.21 79.81 0 bottom
PC4205  SC1U50V5ZY-1-GP-U  [C805H58]  189.31 150.44 0 top
PC4206  SC100P50V2JN-3GP  [C402H22]  184.41 80.24 90 bottom
PC4409  SCD1U10V2MX-3GP  [C402H22]  128.04 137.69 270 top
PC4410  SCD1U16V2KX-3GP  [C402H22]  136.5 137.54 180 top
PC4411  SC330P50V2KX-3GP  [C402H22]  138.02 131.85 180 top
PC4412  SC47P50V2JN-3GP  [C402H22]  136.91 129.79 180 top
PC4413  SC1KP50V2KX-1GP  [C402H22]  138.4 129.18 90 top
PC4414  SC1KP25V2JX-GP  [C402H22]  140.18 135 180 top
PC4415  SC3300P50V2KX-1GP  [C402H22]  138.53 133.35 90 top
PC4416  SCD1U16V2KX-3GP  [C402H22]  126.92 131.67 270 top
PC4417  SC470P50V2KX-3GP  [C402H22]  132.82 130.43 0 bottom
PC4418  SC1KP50V2KX-1GP  [C402H22]  128.32 127.38 0 top
PC4419  SC470P50V2KX-3GP  [C402H22]  134.34 126.75 90 top
PC4420  SC680P50V2KX-2GP  [C402H22]  134.37 125.81 90 top
PC4421  SCD22U25V3KX-GP  [C603H40]  126.26 133.71 270 top
PC4422  SC1U10V2KX-1GP  [C402H22]  133.07 139.19 180 top
PC4423  SCD1U25V2KX-GP  [C402H22]  113 134.57 90 top
PC4424  SC10U25V5KX-GP  [C805H56]  113.11 136.02 90 top
PC4426  SC2D2U10V3KX-1GP  [C603H36]  124.59 128.47 270 top
PC4427  SCD01U50V2KX-1GP  [C402H22]  126.62 137.24 180 top
PC4428  SCD1U16V2KX-3GP  [C402H22]  138.15 136.91 90 top
PC4429  SC1KP50V2KX-1GP  [C402H22]  112.27 132.33 180 top
PC4431  SC10U25V5KX-GP  [C805H56]  113.13 135.79 270 bottom
PC4509  SCD1U10V2MX-3GP  [C402H22]  40.51 72.06 0 bottom
PC4510  SCD1U16V2KX-3GP  [C402H22]  38.48 72.77 0 bottom
PC4511  SC330P50V2KX-3GP  [C402H22]  33.15 75.18 180 bottom
PC4512  SC47P50V2JN-3GP  [C402H22]  33.71 76.81 270 top
PC4513  SC1KP50V2KX-1GP  [C402H22]  34.21 78.26 180 top
PC4514  SC1KP25V2JX-GP  [C402H22]  33.58 71.91 90 top
PC4515  SC3300P50V2KX-1GP  [C402H22]  33.71 73.84 270 top
PC4516  SCD1U16V2KX-3GP  [C402H22]  43.69 77.22 90 top
PC4517  SC470P50V2KX-3GP  [C402H22]  37.39 78.77 90 top
PC4518  SC1KP50V2KX-1GP  [C402H22]  41.33 81.28 180 top
PC4519  SC470P50V2KX-3GP  [C402H22]  38.66 81.53 270 top
PC4520  SC680P50V2KX-2GP  [C402H22]  38.66 80.64 270 top
PC4521  SCD22U25V3KX-GP  [C603H40]  46.23 72.64 0 top
PC4522  SC1U10V2KX-1GP  [C402H22]  131.29 139.7 270 top
PC4523  SCD1U25V2KX-GP  [C402H22]  50.16 61.59 270 top
PC4524  SC10U25V5KX-GP  [C805H56]  50.39 70.1 180 top
PC4526  SC2D2U10V3KX-1GP  [C603H36]  43.48 82.58 180 top
PC4527  SCD01U50V2KX-1GP  [C402H22]  42.62 70.05 0 top
PC4528  SCD1U16V2KX-3GP  [C402H22]  37.59 72.77 0 bottom
PC4529  SC1KP50V2KX-1GP  [C402H22]  53.34 70.38 270 top
PC4531  SC10U25V5KX-GP  [C805H56]  50.39 70.1 0 bottom
PC4701  SCD1U16V2KX-3GP  [C402H22]  75.41 125.3 90 top
PC4702  SC1U10V2KX-1GP  [C402H22]  69.74 120.85 0 top
PC4703  SCD1U50V3KX-GP  [C603H36]  72.49 121.18 270 top
PC4704  SC1KP50V2KX-1GP  [C402H22]  84.27 126.92 135 bottom
PC4705  SC22P50V2JN-4GP  [C402H22]  67.93 124.31 90 top
PC4706  SC10U25V5KX-GP  [C805H56]  82.73 127.53 315 top
PC4707  SCD1U16V2KX-3GP  [C402H22]  81.05 116.15 225 top
PC4708  SC10U6D3V3MX-GP  [C603H38]  81.94 117.04 225 top
PC4711  SC10U25V5KX-GP  [C805H56]  85.27 130.07 135.3 top
PC4801  SCD1U10V2KX-4GP  [C402H20]  49.12 49.76 90 top
PC4802  SC1U10V2KX-1GP  [C402H22]  50.19 51.28 0 top
PC4803  SCD1U16V2KX-3GP  [C402H22]  55.75 55.88 90 top
PC4804  SC10U6D3V3MX-GP  [C603H38]  54.1 56.77 180 top
PC4805  SC22P50V2JN-4GP  [C402H22]  59.64 53.01 0 top
PC4806  SC10U6D3V3MX-GP  [C603H38]  61.93 52.5 0 top
PC4807  SC10U6D3V3MX-GP  [C603H38]  57.61 56.77 180 top
PC4808  SCD1U16V2KX-3GP  [C402H22]  58.88 56.64 180 top
PC4908  SCD1U25V3KX-GP  [C603H36]  144.79 21.49 90 bottom
PC4909  SC1U10V2KX-1GP  [C402H22]  131.11 19.89 270 bottom
PC4910  SC1U10V2KX-1GP  [C402H22]  154.53 25.86 90 bottom
PC4911  SC22P50V2JN-4-LL-GP  [C402H22]  135.71 16.32 180 bottom
PC4912  SC1U16V3KX-2GP  [C603H36]  146.08 17.05 180 bottom
PC4913  SC22P50V2JN-4-LL-GP  [C402H22]  143.87 17.43 180 bottom
PC4914  SC4D7U6D3V3KX-GP  [C603H36]  143.51 24 0 bottom
PC4915  SC1500P50V3KX-GP  [C603]  143.84 31.23 180 bottom
PC4916  SC1500P50V3KX-GP  [C603]  131.94 34.75 90 bottom
